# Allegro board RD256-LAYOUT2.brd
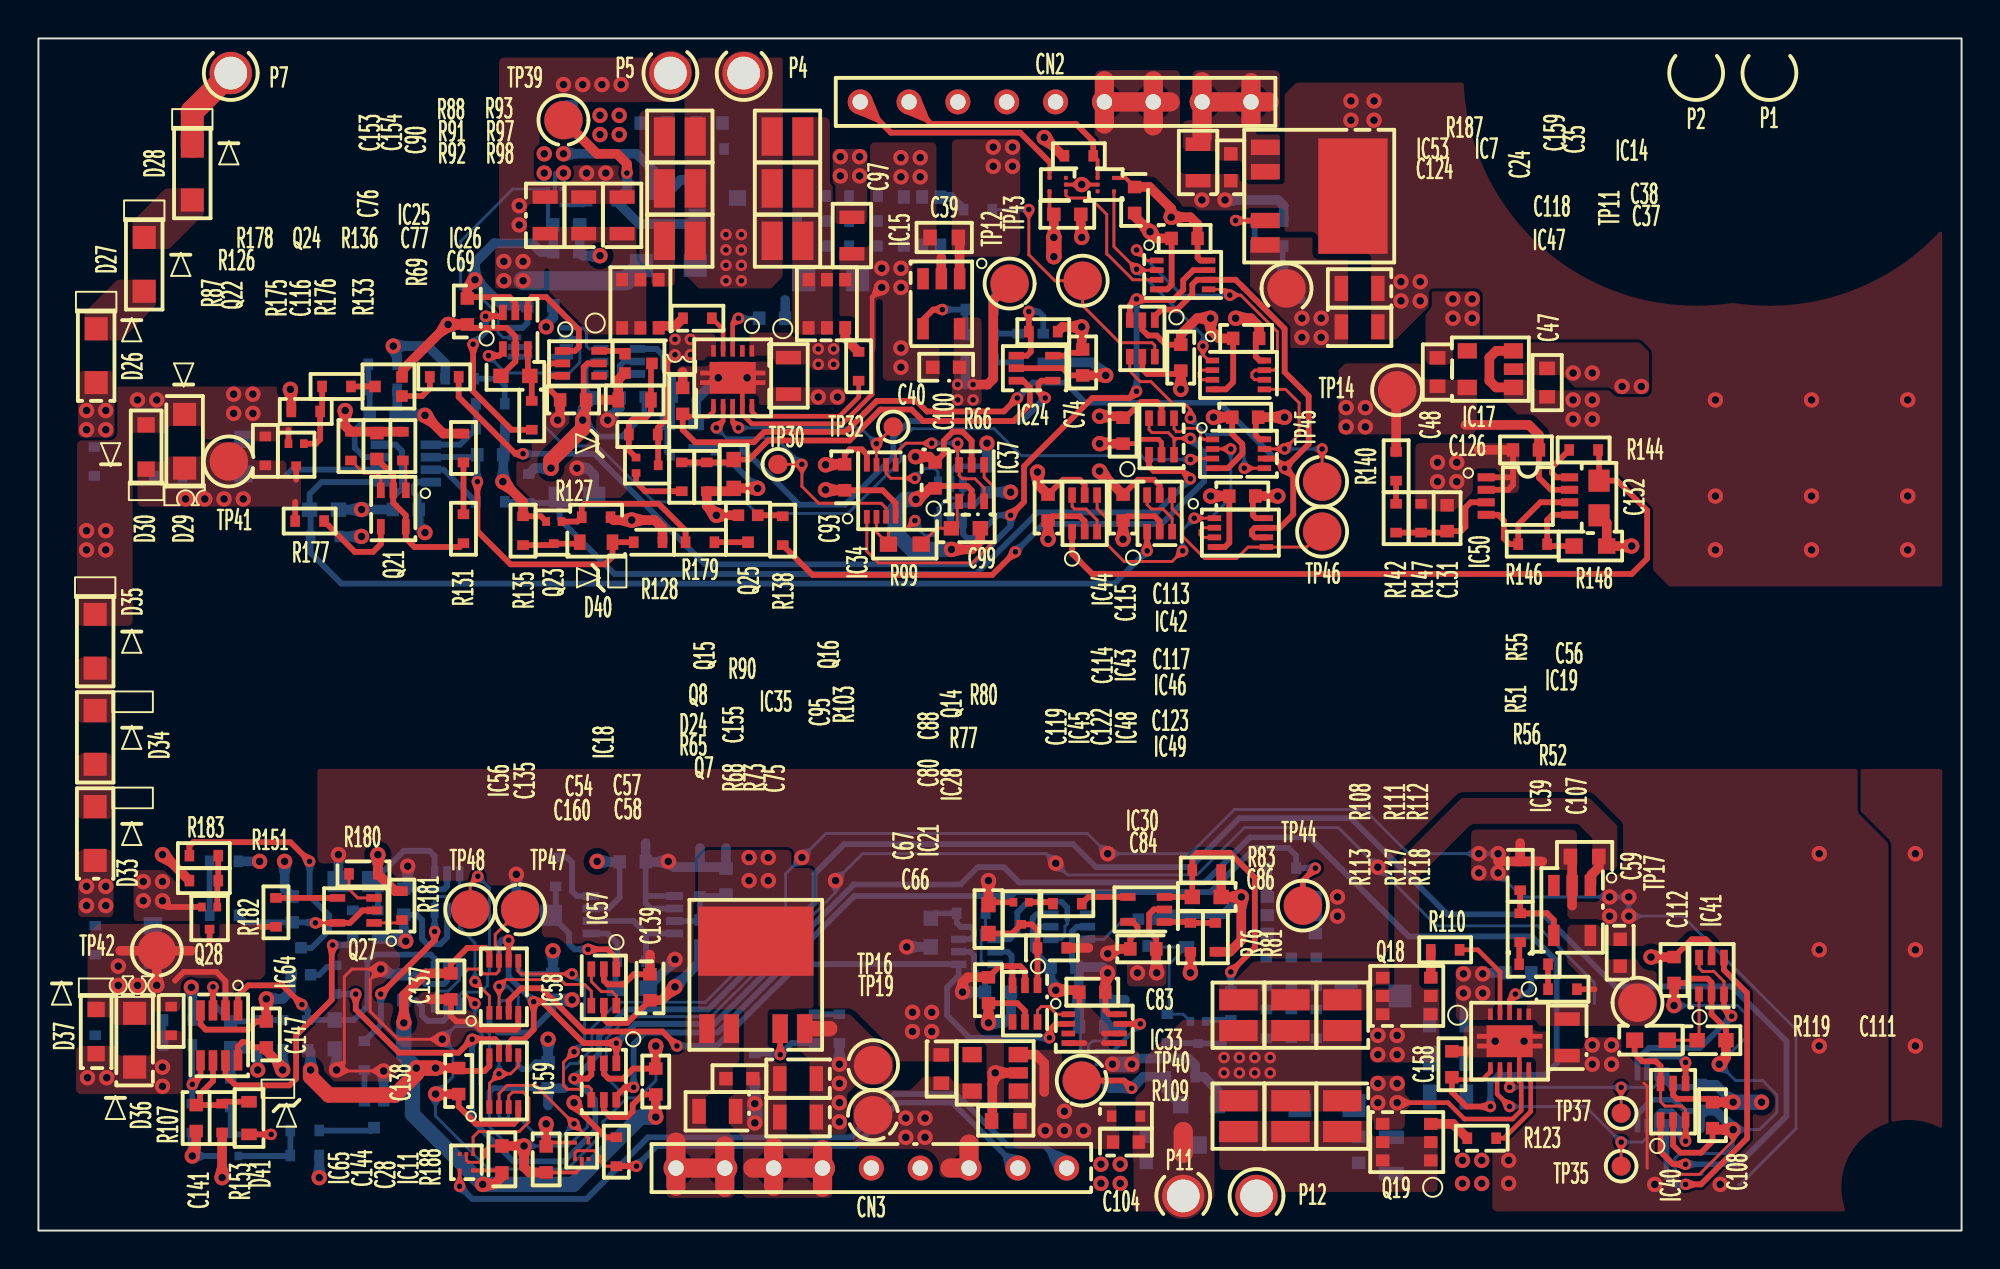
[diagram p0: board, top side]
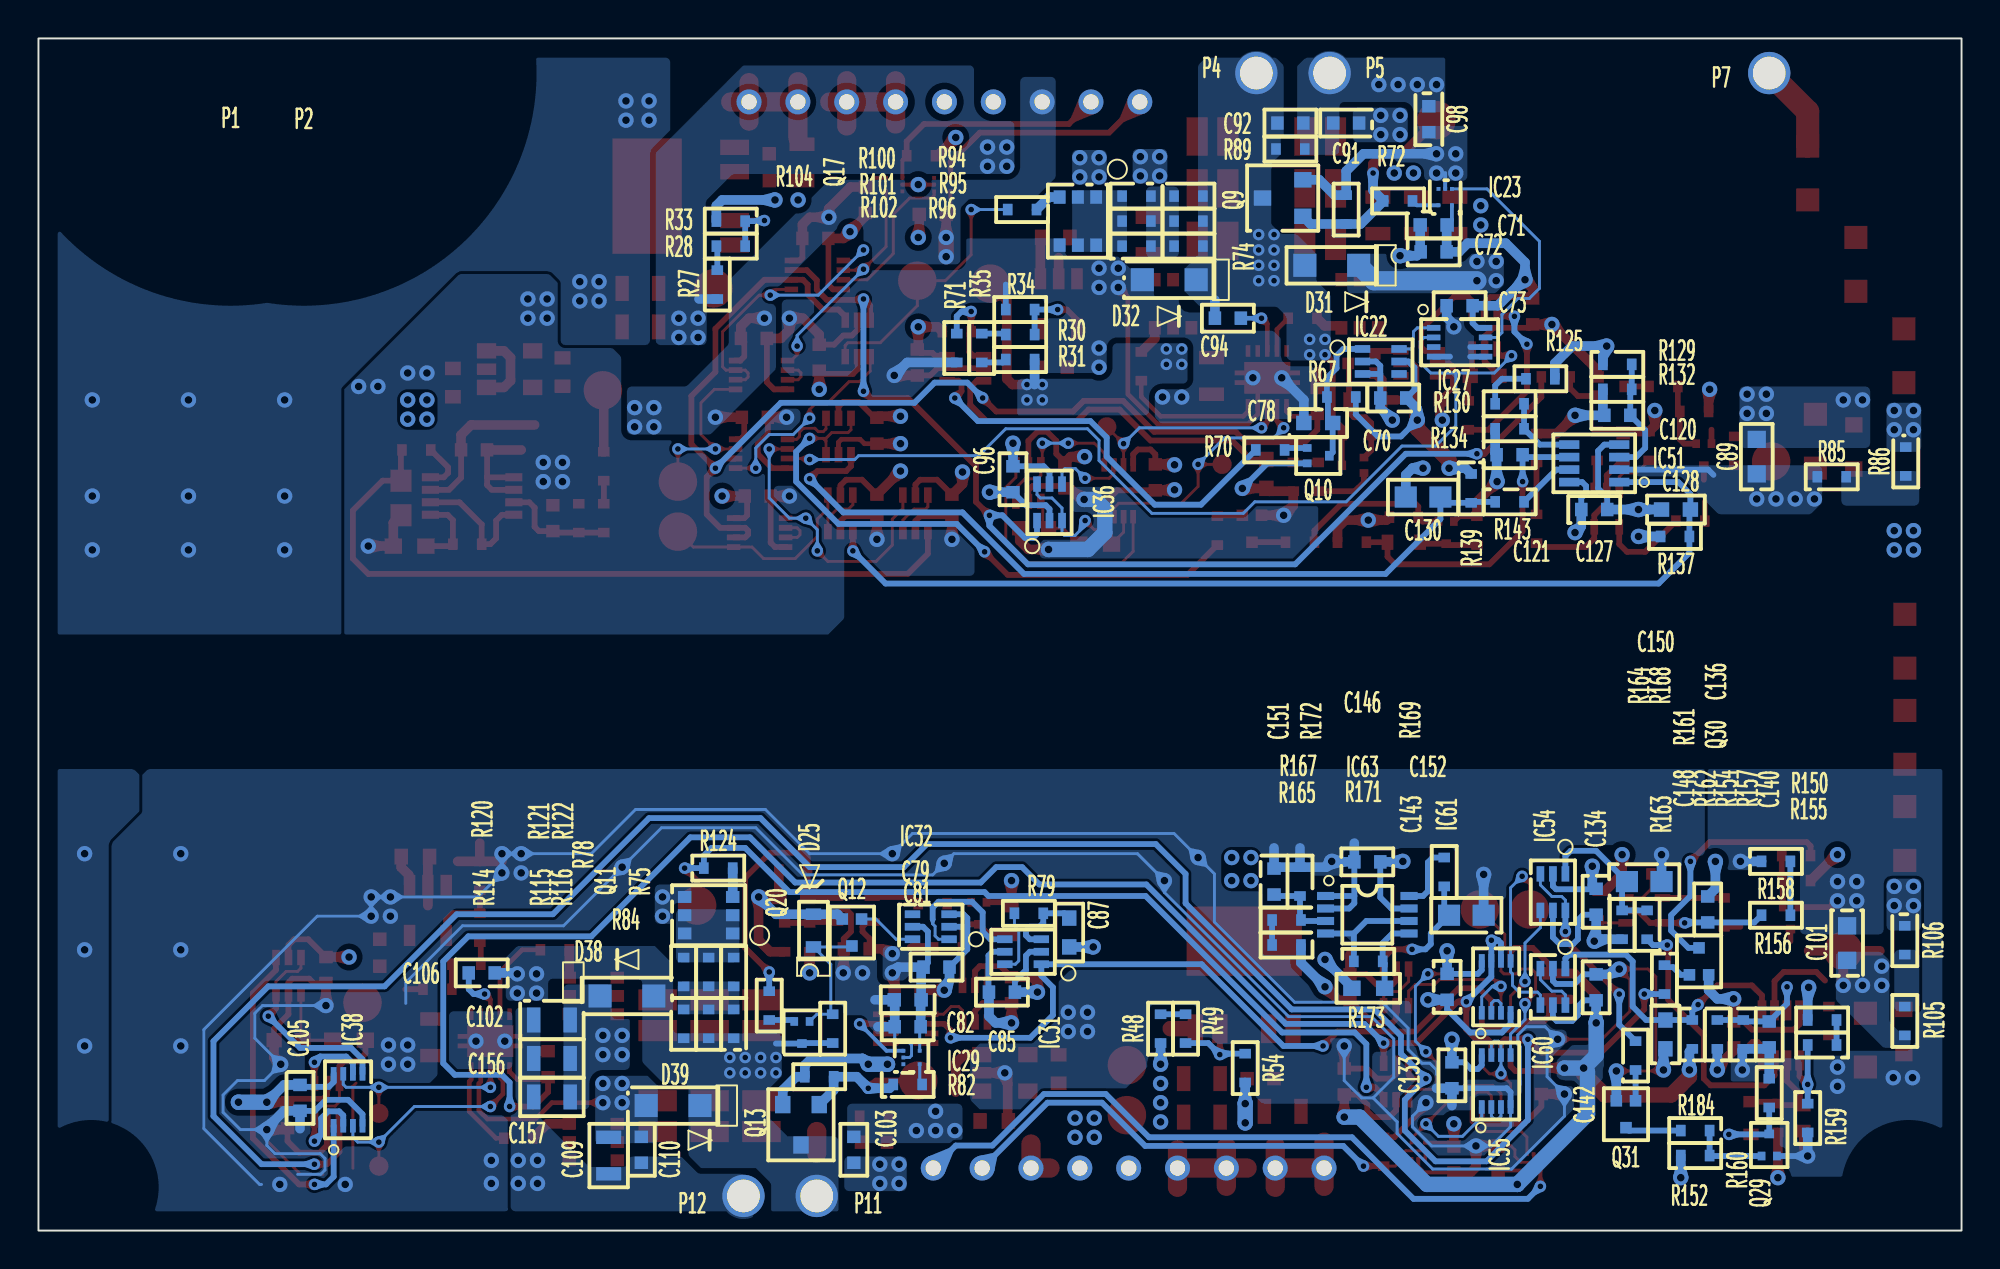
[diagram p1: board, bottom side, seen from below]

Outline 100 x 62 mm; copper layers: TOP, CONDUCTIVE2, CONDUCTIVE3, BOTTOM. Coordinates in mm from the lower left corner of the outline.
Outline path: rectangle 0,0 100,62

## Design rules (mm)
constraint set DEFAULT: 

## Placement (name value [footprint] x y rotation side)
C24  -  [C_CHP_MURATA_L1_6W0_8H0_8A]  57 53.6 270 top
C28  -  [C_CHP_MURATA_L1_6W0_8H0_8A]  26.4 3.7 270 top
C35  -  [C_CHP_TDK_L1_6W0_8H0_8]  62 55.3 90 top
C37  -  [C_CHP_MURATA_L2_0W1_25H1_25]  68.7 47 180 top
C38  -  [C_CHP_MURATA_L2_0W1_25H1_25]  68.7 49 180 top
C39  -  [C_CHP_TYYDN_L1_6W0_8H0_8A]  47.1 51.65 0 top
C40  -  [C_CHP_TDK_L1_6W0_8H0_8]  47.2 44.9 0 top
C47  -  [C_CHP_TYYDN_L1_6W0_8H0_8A]  78.45 44.1 270 top
C48  -  [C_CHP_TYYDN_L1_6W0_8H0_8A]  72.75 44.65 270 top
C54  -  [C_CHP_TDK_L1_6W0_8H0_8]  36.45 7.9 180 top
C56  -  [C_CHP_TYYDN_L1_6W0_8H0_8A]  80.4 19.45 0 top
C57  -  [C_CHP_MURATA_L2_0W1_25H1_25]  39.5 7.9 0 top
C58  -  [C_CHP_MURATA_L2_0W1_25H1_25]  39.5 5.9 0 top
C59  -  [C_CHP_TDK_L1_6W0_8H0_8]  82.25 14.45 270 top
C66  -  [C_CHP_TYYDN_L1_6W0_8H0_8A]  50.3 5.7 0 top
C67  -  [C_CHP_TYYDN_L1_6W0_8H0_8A]  46.95 8.4 270 top
C69  -  [C_CHP_MURATA_L1_6W0_8H0_8A]  27.8 43.2 0 top
C70  -  [C_CHP_MURATA_L1_6W0_8H0_8A]  29.55 43.3 180 bottom
C71  -  [C_CHP_TDK_L1_6W0_8H0_8]  27.45 52.3 180 bottom
C72  -  [C_CHP_MURATA_L1_6W0_8H0_8A]  27.45 50.9 180 bottom
C73  -  [C_CHP_MURATA_L1_6W0_8H0_8A]  26.1 48.1 180 bottom
C74  -  [C_CHP_MURATA_L1_6W0_8H0_8A]  54.3 45.15 90 top
C75  -  [C_CHP_AVX_L1_6W0_81H0_9]  36.15 39.35 90 top
C76  -  [C_CHP_MURATA_L1_6W0_8H0_8A]  22.3 47.8 90 top
C77  -  [C_CHP_AVX_L1_6W0_81H0_9]  24.8 44.45 0 top
C78  -  [C_CHP_AVX_L1_6W0_81H0_9]  33.45 42 180 bottom
C79  -  [C_CHP_MURATA_L1_6W0_8H0_8A]  53.3 13.7 0 bottom
C80  -  [C_CHP_MURATA_L1_6W0_8H0_8A]  49.4 12.5 270 top
C81  -  [C_CHP_TDK_L1_6W0_8H0_8]  54.8 12 180 bottom
C82  -  [C_CHP_MURATA_L1_6W0_8H0_8A]  54.8 10.6 180 bottom
C83  -  [C_CHP_MURATA_L1_6W0_8H0_8A]  54.8 12.4 0 top
C84  -  [C_CHP_MURATA_L1_6W0_8H0_8A]  57.45 14.65 180 top
C85  -  [C_CHP_MURATA_L1_6W0_8H0_8A]  49.9 12.4 0 bottom
C86  -  [C_CHP_AVX_L1_6W0_81H0_9]  60.75 17.35 180 top
C87  -  [C_CHP_AVX_L1_6W0_81H0_9]  46.4 15.5 90 bottom
C88  -  [C_CHP_AVX_L1_6W0_81H0_9]  49.4 16.2 270 top
C89  -  [C_CHP_AVX_L1_6W0_8H0_9]  10.65 40.25 270 bottom
C90  -  [C_CHP_MURATA_L2_0W1_25H1_25]  30.35 52.8 270 top
C91  -  [C_CHP_MURATA_L1_6W0_8H0_8A]  32 57.6 180 bottom
C92  -  [C_CHP_MURATA_L1_6W0_8H0_8A]  34.9 57.6 180 bottom
C93  -  [C_CHP_MURATA_L1_6W0_8H0_8A]  41.92 39.17 90 top
C94  -  [C_CHP_MURATA_L1_6W0_8H0_8A]  38.15 47.45 180 bottom
C95  -  [C_CHP_MURATA_L2_0W1_25H1_25]  39 44.45 90 top
C96  -  [C_CHP_MURATA_L1_6W0_8H0_8A]  49.33 39.08 90 bottom
C97  -  [C_CHP_MURATA_L2_0W1_25H1_25]  42.3 51.75 90 top
C98  -  [C_CHP_MURATA_L1_6W0_8H0_8A]  27.7 57.8 90 bottom
C99  -  [C_CHP_AVX_L1_6W0_81H0_9]  48.23 36.52 180 top
C100  -  [C_CHP_MURATA_L1_6W0_8H0_8A]  46.62 39.27 90 top
C101  -  [C_CHP_AVX_L1_6W0_8H0_9]  5.95 14.95 270 bottom
C102  -  [C_CHP_MURATA_L2_0W1_25H1_25]  73.3 10.95 180 bottom
C103  -  [C_CHP_MURATA_L1_6W0_8H0_8A]  57.6 4.2 270 bottom
C104  -  [C_CHP_MURATA_L1_6W0_8H0_8A]  56.55 4.6 180 top
C105  -  [C_CHP_MURATA_L1_6W0_8H0_8A]  86.4 6.9 90 bottom
C106  -  [C_CHP_MURATA_L1_6W0_8H0_8A]  76.95 13.4 0 bottom
C107  -  [C_CHP_MURATA_L2_0W1_25H1_25]  79.5 10.05 90 top
C108  -  [C_CHP_MURATA_L1_6W0_8H0_8A]  87.05 6 90 top
C109  -  [C_CHP_MURATA_L2_0W1_25H1_25]  70.35 3.9 270 bottom
C110  -  [C_CHP_MURATA_L1_6W0_8H0_8A]  68.65 4.2 270 bottom
C111  -  [C_CHP_AVX_L1_6W0_81H0_9]  87 9.9 180 top
C112  -  [C_CHP_MURATA_L1_6W0_8H0_8A]  85.05 13.55 90 top
C113  -  [C_CHP_MURATA_L1_6W0_8H0_8A]  62.8 46.4 0 top
C114  -  [C_CHP_MURATA_L1_6W0_8H0_8A]  56.4 41.6 270 top
C115  -  [C_CHP_MURATA_L1_6W0_8H0_8A]  59.4 45.4 90 top
C116  -  [C_CHP_MURATA_L1_6W0_8H0_8A]  17.6 40.8 90 top
C117  -  [C_CHP_MURATA_L1_6W0_8H0_8A]  62.75 42.3 0 top
C118  -  [C_CHP_MURATA_L1_6W0_8H0_8A]  59.6 51.6 0 top
C119  -  [C_CHP_MURATA_L1_6W0_8H0_8A]  52.5 37.6 270 top
C120  -  [C_CHP_MURATA_L1_6W0_8H0_8A]  17.9 42.4 180 bottom
C121  -  [C_CHP_MURATA_L1_6W0_8H0_8A]  23.5 40.35 180 bottom
C122  -  [C_CHP_MURATA_L1_6W0_8H0_8A]  56.4 37.6 270 top
C123  -  [C_CHP_MURATA_L1_6W0_8H0_8A]  62.6 38.2 0 top
C124  -  [C_CHP_TDK_L1_6W0_8H0_8]  53.5 52.85 0 top
C126  -  [C_CHP_MURATA_L1_6W0_8H0_8A]  77.35 40.6 0 top
C127  -  [C_CHP_MURATA_L1_6W0_8H0_8A]  19.1 37.5 0 bottom
C128  -  [C_CHP_AVX_L1_6W0_81H0_9]  14.85 37.5 180 bottom
C130  -  [C_CHP_KEMET_L1_6W0_8H0_8]  28 38.15 180 bottom
C131  -  [C_CHP_MURATA_L1_6W0_8H0_8A]  73.25 37.05 270 top
C132  -  [C_CHP_KEMET_L1_6W0_8H0_8]  81.15 38.1 90 top
C133  -  [C_CHP_MURATA_L1_6W0_8H0_8A]  26.5 8.07 90 bottom
C134  -  [C_CHP_MURATA_L1_6W0_8H0_8A]  19 17.1 90 bottom
C135  -  [C_CHP_MURATA_L1_6W0_8H0_8A]  32.1 7.75 90 top
C136  -  [C_CHP_MURATA_L1_6W0_8H0_8A]  13.2 16.7 90 bottom
C137  -  [C_CHP_MURATA_L1_6W0_8H0_8A]  21.45 12.7 90 top
C138  -  [C_CHP_MURATA_L1_6W0_8H0_8A]  21.85 7.78 90 top
C139  -  [C_CHP_MURATA_L1_6W0_8H0_8A]  31.8 12.65 90 top
C140  -  [C_CHP_MURATA_L1_6W0_8H0_8A]  10 10.2 90 bottom
C141  -  [C_CHP_MURATA_L1_6W0_8H0_8A]  8.2 5.85 90 top
C142  -  [C_CHP_MURATA_L1_6W0_8H0_8A]  19 12.65 90 bottom
C143  -  [C_CHP_MURATA_L1_6W0_8H0_8A]  26.75 12.68 90 bottom
C144  -  [C_CHP_TDK_L1_6W0_8H0_8]  24.1 3.7 90 top
C146  -  [C_CHP_MURATA_L1_6W0_8H0_8A]  30.9 19.18 180 bottom
C147  -  [C_CHP_MURATA_L1_6W0_8H0_8A]  11.85 10.2 270 top
C148  -  [C_CHP_AVX_L1_6W0_81H0_9]  15.4 10.2 90 bottom
C150  -  [C_CHP_KEMET_L1_6W0_8H0_8]  16.5 18.15 0 bottom
C151  -  [C_CHP_MURATA_L1_6W0_8H0_8A]  35.75 18.15 270 bottom
C152  -  [C_CHP_KEMET_L1_6W0_8H0_8]  25.75 16.4 0 bottom
C153  -  [C_CHP_MURATA_L2_0W1_25H1_25]  26.35 52.8 270 top
C154  -  [C_CHP_MURATA_L2_0W1_25H1_25]  28.35 52.8 270 top
C155  -  [C_CHP_MURATA_L1_6W0_8H0_8A]  33.5 43.15 90 top
C156  -  [C_CHP_MURATA_L2_0W1_25H1_25]  73.3 8.95 180 bottom
C157  -  [C_CHP_MURATA_L2_0W1_25H1_25]  73.3 6.95 180 bottom
C158  -  [C_CHP_MURATA_L1_6W0_8H0_8A]  73.5 8.65 90 top
C159  -  [C_CHP_MURATA_L2_0W1_25H1_25]  60.3 55.55 90 top
C160  -  [C_CHP_MURATA_L2_0W1_25H1_25]  35.3 6.2 180 top
CN2  -  [PM_61_9P]  63.05 58.7 180 top
CN3  -  [PM_61_9P]  33.15 3.25 0 top
D24  -  [ZD_SMD_TSB_K_1_A_2_L1_2W0_8H0_6]  31 43.2 180 top
D25  -  [ZD_SMD_TSB_K_1_A_2_L1_2W0_8H0_6]  59.7 15.6 90 bottom
D26  -  [D_SMD_TSB_K_2_A_1_L2_6W1_6H0_98]  3 45.5 270 top
D27  -  [D_SMD_TSB_K_2_A_1_L2_6W1_6H0_98]  5.5 50.25 270 top
D28  -  [D_SMD_TSB_K_2_A_1_L2_6W1_6H0_98]  8 55 270 top
D29  -  [D_SMD_TSB_K_2_A_1_L2_6W1_6H0_98]  7.6 41.05 90 top
D30  -  [D_SMD_TSB_K_2_A_1_L1_7W1_25H0_9]  5.6 40.75 90 top
D31  -  [D_SMD_TSB_K_2_A_1_L2_6W1_6H0_98]  32.75 50.2 0 bottom
D32  -  [D_SMD_TSB_K_2_A_1_L2_6W1_6H0_98]  41.2 49.45 0 bottom
D33  -  [D_SMD_TSB_K_2_A_1_L2_6W1_6H0_98]  2.95 20.65 270 top
D34  -  [D_SMD_TSB_K_2_A_1_L2_6W1_6H0_98]  2.95 25.65 270 top
D35  -  [D_SMD_TSB_K_2_A_1_L2_6W1_6H0_98]  2.95 30.65 270 top
D36  -  [D_SMD_TSB_K_2_A_1_L2_6W1_6H0_98]  5 9.9 270 top
D37  -  [D_SMD_TSB_K_2_A_1_L1_7W1_25H0_9]  3 10.35 270 top
D38  -  [D_SMD_TSB_K_2_A_1_L2_6W1_6H0_98]  69.4 12.2 180 bottom
D39  -  [D_SMD_TSB_K_2_A_1_L2_6W1_6H0_98]  67 6.5 0 bottom
D40  -  [ZD_SMD_TSB_K_1_A_2_L1_2W0_8H0_6]  29 35.8 180 top
D41  -  [ZD_SMD_TSB_K_1_A_2_L1_2W0_8H0_6]  10.95 5.85 270 top
IC7  -  [IC_SMD_5_TSB_L1_0W0_8H0_48_RCNT]  55.5 54.4 270 top
IC11  -  [IC_SMD_5_TSB_L1_0W0_8H0_48_RCNT]  28.25 4.15 0 top
IC14  -  [REG_TO_252_5S_A_ABLIC_L6_5W4_7H1_4]  67.1 53.8 270 top
IC15  -  [IC_SOP_5_TI_L3_05W1_75H1_45]  46.95 48.2 180 top
IC17  -  [IC_SC74A_TSB_L2_9W1_6H1_15_RP0_05]  75.5 44.8 90 top
IC18  -  [REG_TO_252_5S_A_ABLIC_L6_5W4_7H1_4]  37.3 13.8 0 top
IC19  -  [IC_SOP_5_TI_L3_05W1_75H1_45]  79.75 16.65 180 top
IC21  -  [IC_SC74A_TSB_L2_9W1_6H1_15_RP0_05]  49.75 8.2 90 top
IC22  -  [IC_SOP_6_TSB_L2_0W1_25H0_95_RP0_05]  30.2 45.2 270 bottom
IC23  -  [IC_SMD_5_TSB_L1_0W0_8H0_48_RCNT]  26.85 53.75 0 bottom
IC24  -  [IC_SC88A_TSB_L2_0W1_25H0_95_RP0_05]  51.8 44.85 270 top
IC25  -  [IC_SOP_6_TSB_L2_0W1_25H0_95_RP0_05]  24.8 46.8 0 top
IC26  -  [IC_SOP_6_TSB_L2_0W1_25H0_95_RP0_05]  28.2 45.1 270 top
IC27  -  [IC_SOP_8_TSB_L2_0W2_3H0_75_P0_5_RP0_05]  26.1 46.2 270 bottom
IC28  -  [IC_SOP_6_TSB_L2_0W1_25H0_95_RP0_05]  51.3 11.8 180 top
IC29  -  [IC_SMD_5_TSB_L1_0W0_8H0_48_RCNT]  54.6 9 270 bottom
IC30  -  [IC_SC88A_TSB_L2_0W1_25H0_95_RP0_05]  57.6 16.7 90 top
IC31  -  [IC_SOP_6_TSB_L2_0W1_25H0_95_RP0_05]  48.8 14.5 90 bottom
IC32  -  [IC_SOP_6_TSB_L2_0W1_25H0_95_RP0_05]  53.6 15.8 90 bottom
IC33  -  [IC_SOP_8_TSB_L2_0W2_3H0_75_P0_5_RP0_05]  54.9 10.5 270 top
IC34  -  [IC_SOP_8_TSB_L2_0W2_3H0_75_P0_5_RP0_05]  43.83 38.48 0 top
IC35  -  [IC_SON_10S1_TI_L3_1W3_1H1_0_RP0_05_2]  36.1 44.35 180 top
IC36  -  [IC_SOP_6_TSB_L2_0W1_25H0_95_RP0_05]  47.42 37.88 180 bottom
IC37  -  [IC_SOP_6_TSB_L2_0W1_25H0_95_RP0_05]  48.52 38.88 0 top
IC38  -  [IC_SOP_8_TSB_L2_0W2_3H0_75_P0_5_RP0_05]  83.9 6.8 180 bottom
IC39  -  [IC_SON_10S1_TI_L3_1W3_1H1_0_RP0_05_2]  76.5 9.85 180 top
IC40  -  [IC_SOP_6_TSB_L2_0W1_25H0_95_RP0_05]  85 6.7 0 top
IC41  -  [IC_SOP_6_TSB_L2_0W1_25H0_95_RP0_05]  87 13.25 0 top
IC42  -  [IC_SOP_8_TSB_L2_0W2_3H0_75_P0_5_RP0_05]  62.4 44.5 270 top
IC43  -  [IC_SOP_6_TSB_L2_0W1_25H0_95_RP0_05]  58.4 41.3 0 top
IC44  -  [IC_SOP_6_TSB_L2_0W1_25H0_95_RP0_05]  57.4 46.4 180 top
IC45  -  [IC_SOP_6_TSB_L2_0W1_25H0_95_RP0_05]  54.4 37.3 0 top
IC46  -  [IC_SOP_8_TSB_L2_0W2_3H0_75_P0_5_RP0_05]  62.4 40.4 270 top
IC47  -  [IC_SOP_8_TSB_L2_0W2_3H0_75_P0_5_RP0_05]  59.5 49.7 270 top
IC48  -  [IC_SOP_6_TSB_L2_0W1_25H0_95_RP0_05]  58.3 37.3 0 top
IC49  -  [IC_SOP_8_TSB_L2_0W2_3H0_75_P0_5_RP0_05]  62.5 36.3 270 top
IC50  -  [IC_MS8_LINEAR_L3_0W3_0H1_1_P0_65]  77.45 38.2 270 top
IC51  -  [IC_DDF_TI_L2_9W1_6H1_1_P0_65]  19.1 39.9 90 bottom
IC53  -  [IC_SMD_5_TSB_L1_0W0_8H0_48_RCNT]  53 54.4 90 top
IC54  -  [IC_SOP_6_TSB_L2_0W1_25H0_95_RP0_05]  21.25 17.6 0 bottom
IC55  -  [IC_SOP_8_TSB_L2_0W2_3H0_75_P0_5_RP0_05]  24.2 7.78 180 bottom
IC56  -  [IC_SOP_6_TSB_L2_0W1_25H0_95_RP0_05]  29.4 7.75 180 top
IC57  -  [IC_SOP_6_TSB_L2_0W1_25H0_95_RP0_05]  29.4 12.65 180 top
IC58  -  [IC_SOP_8_TSB_L2_0W2_3H0_75_P0_5_RP0_05]  24.2 12.68 0 top
IC59  -  [IC_SOP_8_TSB_L2_0W2_3H0_75_P0_5_RP0_05]  24.2 7.78 0 top
IC60  -  [IC_SOP_6_TSB_L2_0W1_25H0_95_RP0_05]  21.25 12.68 0 bottom
IC61  -  [IC_SOP_8_TSB_L2_0W2_3H0_75_P0_5_RP0_05]  24.2 12.68 180 bottom
IC63  -  [IC_MS8_LINEAR_L3_0W3_0H1_1_P0_65]  30.9 16.43 270 bottom
IC64  -  [IC_DDF_TI_L2_9W1_6H1_1_P0_65]  9.4 10.15 180 top
IC65  -  [IC_SMD_5_TSB_L1_0W0_8H0_48_RCNT]  22.25 3.55 180 top
NOREF  -  []  86.2 60.2 90 top
NOREF#2  -  []  90.01 60.2 90 top
P4  -  [ITNS_TH1_7_P_C2_2_RP0_05]  36.67 60.2 0 top
P5  -  [ITNS_TH1_7_P_C2_2_RP0_05]  32.86 60.2 0 top
P7  -  [ITNS_TH1_7_P_C2_2_RP0_05]  10 60.2 0 top
P11  -  [ITNS_TH1_7_P_C2_2_RP0_05]  59.53 1.8 0 top
P12  -  [ITNS_TH1_7_P_C2_2_RP0_05]  63.34 1.8 0 top
Q7  -  [TR_SMD_3_TSB_B_1_E_2_C_3_L1_2W0_8H0_5]  31.65 39.8 270 top
Q8  -  [FET_SMD_TSB_G_1_S_2_D_3_L1_6W0_8H0_75]  31.2 45.1 270 top
Q9  -  [FET_SMD_TSB_L2_9W1_8H0_8]  35.3 53.7 90 bottom
Q10  -  [TR_SMD_3_TSB_B_1_E_2_C_3_L1_2W0_8H0_5]  33.45 40.3 270 bottom
Q11  -  [TR_SMD_3_TSB_B_1_E_2_C_3_L1_2W0_8H0_5]  60.3 10.3 0 bottom
Q12  -  [FET_SMD_TSB_G_1_S_2_D_3_L1_6W0_8H0_75]  57.7 15.5 0 bottom
Q13  -  [FET_SMD_TSB_L2_9W1_8H0_8]  60.35 5.5 0 bottom
Q14  -  [TR_SMD_3_TSB_B_1_E_2_C_3_L1_2W0_8H0_5]  51.1 16.5 180 top
Q15  -  [FET_SMD_TSB_D_1_2_5_6_G_3_S_4_L2_9W2_2H0_8_RP0_05]  31.3 48.2 0 top
Q16  -  [FET_SMD_TSB_D_1_2_5_6_G_3_S_4_L2_9W2_2H0_8_RP0_05]  41 48.2 0 top
Q17  -  [FET_SMD_TSB_D_1_2_5_6_G_3_S_4_L2_9W2_2H0_8_RP0_05]  45.95 52.5 0 bottom
Q18  -  [FET_SMD_TSB_D_1_2_5_6_G_3_S_4_L2_9W2_2H0_8_RP0_05]  71.15 12.2 90 top
Q19  -  [FET_SMD_TSB_D_1_2_5_6_G_3_S_4_L2_9W2_2H0_8_RP0_05]  71.15 4.6 90 top
Q20  -  [FET_SMD_TSB_D_1_2_5_6_G_3_S_4_L2_9W2_2H0_8_RP0_05]  65.15 16.4 90 bottom
Q21  -  [TR_USV_TSB_L2_0W1_25H1_1]  18.45 37.55 180 top
Q22  -  [TR_SMD_3_TSB_B_1_E_2_C_3_L1_2W0_8H0_5]  13.4 40.35 180 top
Q23  -  [TR_SMD_3_TSB_B_1_E_2_C_3_L1_2W0_8H0_5]  26.8 36.3 180 top
Q24  -  [FET_SMD_TSB_G_1_S_2_D_3_L1_6W0_8H0_75]  18.2 43.9 90 top
Q25  -  [FET_SMD_TSB_G_1_S_2_D_3_L1_6W0_8H0_75]  36.9 36.5 180 top
Q27  -  [TR_USV_TSB_L2_0W1_25H1_1]  16.5 16.65 90 top
Q28  -  [TR_SMD_3_TSB_B_1_E_2_C_3_L1_2W0_8H0_5]  8.9 16.25 180 top
Q29  -  [TR_SMD_3_TSB_B_1_E_2_C_3_L1_2W0_8H0_5]  10 4.45 180 bottom
Q30  -  [FET_SMD_TSB_G_1_S_2_D_3_L1_6W0_8H0_75]  13.65 14 180 bottom
Q31  -  [FET_SMD_TSB_G_1_S_2_D_3_L1_6W0_8H0_75]  17.45 6.05 0 bottom
R27  -  [R_CHP_KOA_L1_6W0_8H0_45]  64.7 49.2 270 bottom
R28  -  [R_CHP_KOA_L1_6W0_8H0_45]  64 51.2 0 bottom
R30  -  [R_CHP_KOA_L1_6W0_8H0_45]  48.95 46.6 0 bottom
R31  -  [R_CHP_KOA_L1_6W0_8H0_45]  48.95 45.3 180 bottom
R33  -  [R_CHP_KOA_L1_6W0_8H0_45]  64 52.5 180 bottom
R34  -  [R_CHP_KOA_L1_6W0_8H0_45]  48.95 47.9 180 bottom
R35  -  [R_CHP_KOA_L1_6W0_8H0_45]  50.95 45.9 270 bottom
R48  -  [R_CHP_KOA_L1_6W0_8H0_45]  41.65 10.5 270 bottom
R49  -  [R_CHP_KOA_L1_6W0_8H0_45]  40.35 10.5 90 bottom
R51  -  [R_CHP_KOA_L1_6W0_8H0_45]  77.05 15.75 270 top
R52  -  [R_CHP_KOA_L1_6W0_8H0_45]  79.25 12.55 0 top
R54  -  [R_CHP_KOA_L1_6W0_8H0_45]  37.25 8.45 90 bottom
R55  -  [R_CHP_KOA_L1_6W0_8H0_45]  77.05 18.45 270 top
R56  -  [R_CHP_KOA_L1_6W0_8H0_45]  77.75 13.85 0 top
R65  -  [R_CHP_KOA_L1_6W0_8H0_45]  31.45 41.4 0 top
R66  -  [R_CHP_KOA_L1_6W0_8H0_45]  52.25 46.75 0 top
R67  -  [R_CHP_KOA_L1_6W0_8H0_45]  32.25 43.35 180 bottom
R68  -  [R_CHP_KOA_L1_6W0_8H0_45]  33.45 39.2 270 top
R69  -  [R_CHP_KOA_L1_6W0_8H0_45]  25.65 42.4 90 top
R70  -  [R_CHP_KOA_L1_6W0_8H0_45]  35.95 40.6 0 bottom
R71  -  [R_CHP_KOA_L1_6W0_8H0_45]  52.25 45.9 90 bottom
R72  -  [R_CHP_KOA_L1_6W0_8H0_45]  29.3 53.55 0 bottom
R73  -  [R_CHP_KOA_L1_6W0_8H0_45]  34.75 39.2 90 top
R74  -  [R_CHP_KOA_L1_6W0_8H0_45]  32 53.1 270 bottom
R75  -  [R_CHP_KOA_L1_6W0_8H0_45]  58.7 10.5 270 bottom
R76  -  [R_CHP_KOA_L1_6W0_8H0_45]  59.9 15.25 270 top
R77  -  [R_CHP_KOA_L1_6W0_8H0_45]  52.7 14.7 0 top
R78  -  [R_CHP_KOA_L1_6W0_8H0_45]  62 11.7 270 bottom
R79  -  [R_CHP_KOA_L1_6W0_8H0_45]  48.5 16.5 180 bottom
R80  -  [R_CHP_KOA_L1_6W0_8H0_45]  53.5 17 0 top
R81  -  [R_CHP_KOA_L1_6W0_8H0_45]  61.2 15.25 90 top
R82  -  [R_CHP_KOA_L1_6W0_8H0_45]  54.8 7.6 0 bottom
R83  -  [R_CHP_KOA_L1_6W0_8H0_45]  60.75 18.75 180 top
R84  -  [R_CHP_KOA_L1_6W0_8H0_45]  59.4 8 180 bottom
R85  -  [R_CHP_KOA_L1_6W0_8H0_45]  6.75 39.2 180 bottom
R86  -  [R_CHP_KOA_L1_6W0_8H0_45]  2.9 40 90 bottom
R87  -  [R_CHP_KOA_L1_6W0_8H0_45]  11.8 40.55 270 top
R88  -  [R_CHP_ROHM_L2_0W1_2H0_55]  33.35 56.9 270 top
R89  -  [R_CHP_KOA_L1_6W0_8H0_45]  34.9 56.25 180 bottom
R90  -  [R_CHP_KOA_L1_6W0_8H0_45]  34.27 47.45 180 top
R91  -  [R_CHP_ROHM_L2_0W1_2H0_55]  33.35 54.2 270 top
R92  -  [R_CHP_ROHM_L2_0W1_2H0_55]  33.35 51.48 270 top
R93  -  [R_CHP_ROHM_L2_0W1_2H0_55]  38.95 56.9 90 top
R94  -  [R_CHP_KOA_L1_6W0_8H0_45]  40.2 53.8 180 bottom
R95  -  [R_CHP_KOA_L1_6W0_8H0_45]  40.2 52.5 180 bottom
R96  -  [R_CHP_KOA_L1_6W0_8H0_45]  40.2 51.2 180 bottom
R97  -  [R_CHP_ROHM_L2_0W1_2H0_55]  38.95 54.2 90 top
R98  -  [R_CHP_ROHM_L2_0W1_2H0_55]  38.95 51.48 90 top
R99  -  [R_CHP_YAGEO_L1_6W0_8H0_45]  45.05 35.7 0 top
R100  -  [R_CHP_KOA_L1_6W0_8H0_45]  42.9 53.8 180 bottom
R101  -  [R_CHP_KOA_L1_6W0_8H0_45]  42.9 52.5 180 bottom
R102  -  [R_CHP_KOA_L1_6W0_8H0_45]  42.9 51.2 180 bottom
R103  -  [R_CHP_KOA_L1_6W0_8H0_45]  42.65 44.95 90 top
R104  -  [R_CHP_KOA_L1_6W0_8H0_45]  48.85 53.1 180 bottom
R105  -  [R_CHP_KOA_L1_6W0_8H0_45]  2.95 10.9 90 bottom
R106  -  [R_CHP_KOA_L1_6W0_8H0_45]  2.95 15.1 90 bottom
R107  -  [R_CHP_KOA_L1_6W0_8H0_45]  6.9 10.9 90 top
R108  -  [R_CHP_ROHM_L2_0W1_2H0_55]  62.4 11.2 180 top
R109  -  [R_CHP_KOA_L1_6W0_8H0_45]  56.55 5.95 180 top
R110  -  [R_CHP_KOA_L1_6W0_8H0_45]  73.15 14.6 180 top
R111  -  [R_CHP_ROHM_L2_0W1_2H0_55]  65.1 11.2 180 top
R112  -  [R_CHP_ROHM_L2_0W1_2H0_55]  67.8 11.2 180 top
R113  -  [R_CHP_ROHM_L2_0W1_2H0_55]  62.4 5.95 0 top
R114  -  [R_CHP_KOA_L1_6W0_8H0_45]  66.45 10.75 270 bottom
R115  -  [R_CHP_KOA_L1_6W0_8H0_45]  65.15 10.75 270 bottom
R116  -  [R_CHP_KOA_L1_6W0_8H0_45]  63.85 10.75 270 bottom
R117  -  [R_CHP_ROHM_L2_0W1_2H0_55]  65.1 5.95 0 top
R118  -  [R_CHP_ROHM_L2_0W1_2H0_55]  67.8 5.95 0 top
R119  -  [R_CHP_YAGEO_L1_6W0_8H0_45]  83.85 9.9 0 top
R120  -  [R_CHP_KOA_L1_6W0_8H0_45]  66.45 13.45 270 bottom
R121  -  [R_CHP_KOA_L1_6W0_8H0_45]  65.15 13.45 270 bottom
R122  -  [R_CHP_KOA_L1_6W0_8H0_45]  63.85 13.45 270 bottom
R123  -  [R_CHP_KOA_L1_6W0_8H0_45]  75.05 4.8 180 top
R124  -  [R_CHP_KOA_L1_6W0_8H0_45]  64.65 18.85 180 bottom
R125  -  [R_CHP_KOA_L1_6W0_8H0_45]  21.9 44.3 180 bottom
R126  -  [R_CHP_KOA_L1_6W0_8H0_45]  13.9 42.6 180 top
R127  -  [R_CHP_KOA_L1_6W0_8H0_45]  29 37.1 0 top
R128  -  [R_CHP_KOA_L1_6W0_8H0_45]  31.7 35.8 0 top
R129  -  [R_CHP_KOA_L1_6W0_8H0_45]  17.9 45.05 0 bottom
R130  -  [R_CHP_KOA_L1_6W0_8H0_45]  23.5 43 0 bottom
R131  -  [R_CHP_KOA_L1_6W0_8H0_45]  22.1 36.5 270 top
R132  -  [R_CHP_KOA_L1_6W0_8H0_45]  17.9 43.75 180 bottom
R133  -  [R_CHP_KOA_L1_6W0_8H0_45]  22.1 40.7 270 top
R134  -  [R_CHP_KOA_L1_6W0_8H0_45]  23.5 41.7 180 bottom
R135  -  [R_CHP_KOA_L1_6W0_8H0_45]  25.2 36.4 270 top
R136  -  [R_CHP_KOA_L1_6W0_8H0_45]  21.1 44.4 0 top
R137  -  [R_CHP_KOA_L1_6W0_8H0_45]  14.9 36.1 0 bottom
R138  -  [R_CHP_KOA_L1_6W0_8H0_45]  38.7 36.4 270 top
R139  -  [R_CHP_KOA_L1_6W0_8H0_45]  25.5 38.6 90 bottom
R140  -  [R_CHP_KOA_L1_6W0_8H0_45]  70.6 39.75 90 top
R142  -  [R_CHP_KOA_L1_6W0_8H0_45]  70.6 37.05 90 top
R143  -  [R_CHP_KOA_L1_6W0_8H0_45]  23.5 37.9 180 bottom
R144  -  [R_CHP_KOA_L1_6W0_8H0_45]  80.35 40.6 180 top
R146  -  [R_CHP_KOA_L1_6W0_8H0_45]  77.7 35.7 180 top
R147  -  [R_CHP_KOA_L1_6W0_8H0_45]  71.9 37.05 270 top
R148  -  [R_CHP_YAGEO_L1_6W0_8H0_45]  80.7 35.6 180 top
R150  -  [R_CHP_KOA_L1_6W0_8H0_45]  7.25 10.95 0 bottom
R151  -  [R_CHP_KOA_L1_6W0_8H0_45]  8.6 18.2 180 top
R152  -  [R_CHP_KOA_L1_6W0_8H0_45]  13.85 3.9 0 bottom
R153  -  [R_CHP_KOA_L1_6W0_8H0_45]  9.55 5.85 270 top
R154  -  [R_CHP_KOA_L1_6W0_8H0_45]  12.7 10.2 270 bottom
R155  -  [R_CHP_KOA_L1_6W0_8H0_45]  7.25 9.65 180 bottom
R156  -  [R_CHP_KOA_L1_6W0_8H0_45]  9.65 16.4 0 bottom
R157  -  [R_CHP_KOA_L1_6W0_8H0_45]  11.35 10.2 90 bottom
R158  -  [R_CHP_KOA_L1_6W0_8H0_45]  9.65 19.2 180 bottom
R159  -  [R_CHP_KOA_L1_6W0_8H0_45]  8 5.85 90 bottom
R160  -  [R_CHP_KOA_L1_6W0_8H0_45]  10 7.15 270 bottom
R161  -  [R_CHP_KOA_L1_6W0_8H0_45]  15.45 13.05 270 bottom
R162  -  [R_CHP_KOA_L1_6W0_8H0_45]  14 10.2 270 bottom
R163  -  [R_CHP_KOA_L1_6W0_8H0_45]  16.95 9.1 90 bottom
R164  -  [R_CHP_KOA_L1_6W0_8H0_45]  17.65 15.9 270 bottom
R165  -  [R_CHP_KOA_L1_6W0_8H0_45]  35.1 14.85 180 bottom
R167  -  [R_CHP_KOA_L1_6W0_8H0_45]  35.1 16.15 0 bottom
R168  -  [R_CHP_KOA_L1_6W0_8H0_45]  16.35 15.9 270 bottom
R169  -  [R_CHP_KOA_L1_6W0_8H0_45]  26.9 18.65 90 bottom
R171  -  [R_CHP_KOA_L1_6W0_8H0_45]  30.85 14 0 bottom
R172  -  [R_CHP_KOA_L1_6W0_8H0_45]  34.4 18.15 270 bottom
R173  -  [R_CHP_YAGEO_L1_6W0_8H0_45]  30.85 12.6 180 bottom
R175  -  [R_CHP_KOA_L1_6W0_8H0_45]  16.25 40.8 90 top
R176  -  [R_CHP_KOA_L1_6W0_8H0_45]  18.95 40.8 90 top
R177  -  [R_CHP_KOA_L1_6W0_8H0_45]  14.1 36.9 0 top
R178  -  [R_CHP_KOA_L1_6W0_8H0_45]  15.5 43.9 180 top
R179  -  [R_CHP_KOA_L1_6W0_8H0_45]  34.4 35.8 180 top
R180  -  [R_CHP_KOA_L1_6W0_8H0_45]  16.9 18.55 0 top
R181  -  [R_CHP_KOA_L1_6W0_8H0_45]  18.9 16.9 90 top
R182  -  [R_CHP_KOA_L1_6W0_8H0_45]  12.35 16.55 90 top
R183  -  [R_CHP_KOA_L1_6W0_8H0_45]  8.6 19.5 0 top
R184  -  [R_CHP_KOA_L1_6W0_8H0_45]  13.85 5.2 180 bottom
R187  -  [R_CHP_KOA_L1_6W0_8H0_45]  54.1 55.9 0 top
R188  -  [R_CHP_KOA_L1_6W0_8H0_45]  30.05 4.1 270 top
TP11  -  [TPAD_P_C2_0_RP0_05_MN]  64.9 49 180 top
TP12  -  [TPAD_P_C2_0_RP0_05_MN]  50.5 49.25 0 top
TP14  -  [TPAD_P_C2_0_RP0_05_MN]  70.65 43.7 90 top
TP16  -  [TPAD_P_C2_0_RP0_05_MN]  43.4 8.6 270 top
TP17  -  [TPAD_P_C2_0_RP0_05_MN]  83.15 11.85 180 top
TP19  -  [TPAD_P_C2_0_RP0_05_MN]  43.4 6 180 top
TP30  -  [TPAD_P_C1_0_RP0_05_MN]  38.45 39.85 180 top
TP32  -  [TPAD_P_C1_0_RP0_05_MN]  44.45 41.8 180 top
TP35  -  [TPAD_P_C1_0_RP0_05_MN]  82.3 3.35 180 top
TP37  -  [TPAD_P_C1_0_RP0_05_MN]  82.3 6.1 90 top
TP39  -  [TPAD_P_C2_0_RP0_05_MN]  27.3 57.75 0 top
TP40  -  [TPAD_P_C2_0_RP0_05_MN]  54.25 7.8 270 top
TP41  -  [TPAD_P_C2_0_RP0_05_MN]  9.9 40 0 top
TP42  -  [TPAD_P_C2_0_RP0_05_MN]  6.15 14.55 180 top
TP43  -  [TPAD_P_C2_0_RP0_05_MN]  54.3 49.4 270 top
TP44  -  [TPAD_P_C2_0_RP0_05_MN]  65.75 16.9 90 top
TP45  -  [TPAD_P_C2_0_RP0_05_MN]  66.75 38.95 0 top
TP46  -  [TPAD_P_C2_0_RP0_05_MN]  66.75 36.35 270 top
TP47  -  [TPAD_P_C2_0_RP0_05_MN]  25.05 16.7 90 top
TP48  -  [TPAD_P_C2_0_RP0_05_MN]  22.45 16.7 0 top

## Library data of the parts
C24 C28 C69 C70 C72-C74 C76 C79 C80 C82-C85 C91-C94 C96 C98 C100 C103-C106 C108 C110 C112-C115 C117-C119 C122 C123 C126 C127 C133-C135 C137-C139 C142 C143 C146 C147 = GCJ188R71H104KA12D
C35 C40 C54 C59 C71 C81 C124 C144 = C1608X5R1H105K080DB
C37 C38 C57 C58 C95 C107 C159 C160 = GRM21BZ71H475KE15L
C39 C47 C48 C56 C66 C67 = MSASU168SB7474KTNB25
C75 C77 C78 C86-C88 = 06035C680KAT2A
C89 C101 = KGM15ACG2A121KT: alternate symbols: (T:C_CHP_AVX_L1_6W0_8H0_9;B:C_CHP_AVX_L1_6W0_8H0_9,C89_C_CHP_AVX_L1_6W0_8H0_9,C101_C_CHP_AVX_L1_6W0_8H0_9)
C90 C97 C102 C109 C153 C154 C156 C157 = GRM21BR61H106KE43L
C99 C111 = 06035A200KAT2A
C116 C120 C121 C131 C136 C140 C141 C151 = GCD188R71H103KA01D
C128 C148 = 06035C100KAT2A
C130 C132 C150 C152 = C0603C102K5RACTU
C155 C158 = GCM188R71H102KA37D
CN2 CN3 = PM-61-9P
D24 D25 D40 D41 = CEZ5V6,L3F
D26-D28 D33-D35 = CRF03A,LQ(M
D29 D36 = CRZ10(T5L,TEM,Q)
D30 D37 = CUS05F30,H3F(T
D31 D32 D38 D39 = CRS04(TE85L,Q,M)
IC7 IC11 IC23 IC29 IC53 IC65 = TC7SZ04AFS,L3J
IC14 IC18 = S1213B00HV5T2U7
IC15 IC19 = TLV709A01DBVR
IC17 IC21 = TCR1HF50B,LM(CT
IC22 IC25 IC26 IC28 IC31 IC32 IC36 IC37 IC40 IC41 IC43-IC45 IC48 IC54 IC56 IC57 IC60 = TC7PZ14FU,LJ(CT
IC24 IC30 = TC75S57FU(TE85L,F)
IC27 IC33 IC42 IC49 IC55 IC61 = TC7WZ00FK,LJ(CT
IC34 IC38 IC46 IC47 IC58 IC59 = TC7WZ08FK,LJ(CT
IC35 IC39 = UCC27301ADRCR
IC50 IC63 = LTC1440IMS8
IC51 IC64 = LM393BIDDFR
P4 P5 P7 P11 P12 = ITNS-TH1.7-P_C2.2-RP0.05
Q7 Q10 Q11 Q14 Q22 Q23 Q28 Q29 = 2SC5658T2LR
Q8 Q12 Q24 Q25 Q30 Q31 = SSM3K15AFS,LF(T
Q9 Q13 = SSM3K318R,LF(T
Q15-Q20 = SSM6K804R,LF
Q21 Q27 = HN4A56JU
R27 R48 = RK73H1JTTD2003F
R28 R49 R85 R105 = RK73H1JTTD2001F: alternate symbols: (T:R_CHP_KOA_L1_6W0_8H0_45;B:R_CHP_KOA_L1_6W0_8H0_45,R105_R_CHP_KOA_L1_6W0_8H0_45,R85_R_CHP_KOA_L1_6W0_8H0_45)
R30 R34 R51 R55 = RK73H1JTTD1004F
R31 R52 = RK73H1JTTD4704F
R33 R54 = RK73H1JTTD2002F
R35 R56 = RK73H1JTTD3304F
R65 R73-R75 R83 R84 R89 R109 = RK73B1JTTD103J
R66 R69 R71 R76 R79 R81 = RK73B1JTTD512J
R67 R70 R77 R80 = RK73B1JTTD473J
R68 R78 = RK73B1JTTD471J
R72 R82 R94-R96 R100-R102 R114-R116 R120-R122 = RK73B1JTTD100J
R86 R106 = RK73H1JTTD2400F: alternate symbols: (T:R_CHP_KOA_L1_6W0_8H0_45;B:R_CHP_KOA_L1_6W0_8H0_45,R106_R_CHP_KOA_L1_6W0_8H0_45,R86_R_CHP_KOA_L1_6W0_8H0_45)
R87 R90 R103 R107 R110 R123 R177 R182 = RK73Z1JTTD: alternate symbols: (R177_R_CHP_KOA_L1_6W0_8H0_45,R182_R_CHP_KOA_L1_6W0_8H0_45)
R88 R91 R92 R108 R111 R112 = LTR10EZPF1R50
R93 R97 R98 R113 R117 R118 = LTR10EZPF9R10
R99 R119 = RT0603BRC07500RL
R104 R124 = RK73H1JTTD20R0F
R125 R150 = RK73H1JTTD4302F
R126 R127 R137 R139 R151 R152 R162 R164 = RK73B1JTTD303J
R128 R153 R187 R188 = RK73H1JTTD1003F
R129 R154 = RK73H1JTTD1202F
R130 R155 = RK73H1JTTD2201F
R131 R156 = RK73H1JTTD1001F: alternate symbols: (T:R_CHP_KOA_L1_6W0_8H0_45,R131_R_CHP_KOA_L1_6W0_8H0_45;B:R_CHP_KOA_L1_6W0_8H0_45,R156_R_CHP_KOA_L1_6W0_8H0_45)
R132 R157 = RK73H1JTTD8201F
R133 R158 = RK73H1JTTD1002F: alternate symbols: (T:R_CHP_KOA_L1_6W0_8H0_45,R133_R_CHP_KOA_L1_6W0_8H0_45;B:R_CHP_KOA_L1_6W0_8H0_45,R158_R_CHP_KOA_L1_6W0_8H0_45)
R134 R140 R159 R165 = RK73H1JTTD2702F
R135 R160 = RK73H1JTTD3301F
R136 R138 R143 R161 R163 R168 R178 R179 R183 R184 = RK73B1JTTD102J
R142 R167 = RK73H1JTTD3001F
R144 R169 = RK73B1JTTD472J
R146 R171 = RK73H1JTTD1502F
R147 R172 = RK73H1JTTD1802F
R148 R173 = RC0603FR-072M4L
R175 R176 R180 R181 = RK73B1JTTD221J
TP11 TP12 TP14 TP16 TP17 TP19 TP39-TP48 = TPAD-P_C2.0-RP0.05-MN
TP30 TP32 TP35 TP37 = TPAD-P_C1.0-RP0.05-MN

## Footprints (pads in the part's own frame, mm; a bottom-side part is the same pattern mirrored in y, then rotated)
C_CHP_AVX_L1_6W0_8H0_9
  rect 0.9x0.95 smd: 1(-0.9,0) 2(0.9,0)
C_CHP_AVX_L1_6W0_81H0_9
  rect 0.8x0.75 smd: 1(-0.75,0) 2(0.75,0)
C_CHP_KEMET_L1_6W0_8H0_8
  rect 1.15x1.1 smd: 1(-0.9,0) 2(0.9,0)
C_CHP_MURATA_L1_6W0_8H0_8A
  rect 0.65x0.7 smd: 1(-0.675,0) 2(0.675,0)
C_CHP_MURATA_L2_0W1_25H1_25
  rect 0.7x1.3 smd: 1(-0.95,0) 2(0.95,0)
C_CHP_TDK_L1_6W0_8H0_8
  rect 0.7x0.7 smd: 1(-0.7,0) 2(0.7,0)
C_CHP_TYYDN_L1_6W0_8H0_8A
  rect 0.7x0.825 smd: 1(-0.738,0) 2(0.738,0)
D_SMD_TSB_K_2_A_1_L1_7W1_25H0_9
  rect 0.8x0.9 smd: 1(1.15,0) 2(-1.15,0)
D_SMD_TSB_K_2_A_1_L2_6W1_6H0_98
  rect 1.2x1.2 smd: 1(1.4,0) 2(-1.4,0)
FET_SMD_TSB_D_1_2_5_6_G_3_S_4_L2_9W2_2H0_8_RP0_05
  rect 0.62x0.7 smd: 1(-0.95,-1.25) 2(0,-1.25) 3(0.95,-1.25) 4(0.95,1.25) 5(0,1.25) 6(-0.95,1.25)
FET_SMD_TSB_G_1_S_2_D_3_L1_6W0_8H0_75
  rect 0.6x0.6 smd: 1(-0.5,-0.7) 2(0.5,-0.7) 3(0,0.7)
FET_SMD_TSB_L2_9W1_8H0_8
  rect 0.8x0.9 smd: 1(-0.95,-1.05) 2(0.95,-1.05) 3(0,1.05)
IC_DDF_TI_L2_9W1_6H1_1_P0_65
  rect 0.45x1.05 smd: 1(-0.975,-1.3) 2(-0.325,-1.3) 3(0.325,-1.3) 4(0.975,-1.3) 5(0.975,1.3) 6(0.325,1.3) 7(-0.325,1.3) 8(-0.975,1.3)
IC_MS8_LINEAR_L3_0W3_0H1_1_P0_65
  rect 0.42x0.889 smd: 1(-0.975,-2.171) 2(-0.325,-2.171) 3(0.325,-2.171) 4(0.975,-2.171) 5(0.975,2.171) 6(0.325,2.171) 7(-0.325,2.171) 8(-0.975,2.171)
IC_SC74A_TSB_L2_9W1_6H1_15_RP0_05
  rect 0.8x1 smd: 1(-0.95,-1.2) 3(0.95,-1.2) 4(0.95,1.2) 5(-0.95,1.2)
  rect 0.6x1 smd: 2(0,-1.2)
IC_SC88A_TSB_L2_0W1_25H0_95_RP0_05
  rect 0.4x0.8 smd: 1(-0.65,-0.95) 2(0,-0.95) 3(0.65,-0.95) 4(0.65,0.95) 5(-0.65,0.95)
IC_SMD_5_TSB_L1_0W0_8H0_48_RCNT
  rect 0.2x0.2 smd: 1(-0.35,-0.425) 2(0,-0.425) 3(0.35,-0.425) 4(0.35,0.425) 5(-0.35,0.425)
IC_SON_10S1_TI_L3_1W3_1H1_0_RP0_05_2
  rect 0.24x0.6 smd: 1(-1,-1.4) 2(-0.5,-1.4) 3(0,-1.4) 4(0.5,-1.4) 5(1,-1.4) 6(1,1.4) 7(0.5,1.4) 8(0,1.4) 9(-0.5,1.4) 10(-1,1.4)
  custom 0.412x0.412 smd: 11(0,0)
IC_SOP_5_TI_L3_05W1_75H1_45
  rect 0.6x1.1 smd: 1(-0.95,-1.3) 2(0,-1.3) 3(0.95,-1.3) 4(0.95,1.3) 5(-0.95,1.3)
IC_SOP_6_TSB_L2_0W1_25H0_95_RP0_05
  rect 0.4x0.8 smd: 1(-0.65,-0.95) 2(0,-0.95) 3(0.65,-0.95) 4(0.65,0.95) 5(0,0.95) 6(-0.65,0.95)
IC_SOP_8_TSB_L2_0W2_3H0_75_P0_5_RP0_05
  rect 0.3x0.7 smd: 1(-0.75,-1.35) 2(-0.25,-1.35) 3(0.25,-1.35) 4(0.75,-1.35) 5(0.75,1.35) 6(0.25,1.35) 7(-0.25,1.35) 8(-0.75,1.35)
ITNS_TH1_7_P_C2_2_RP0_05
  round 2.2 hole 1.7: 1(0,0)
PM_61_9P
  round 1.3 hole 0.8: 1(0,0) 2(2.54,0) 3(5.08,0) 4(7.62,0) 5(10.16,0) 6(12.7,0) 7(15.24,0) 8(17.78,0) 9(20.32,0)
R_CHP_KOA_L1_6W0_8H0_45
  rect 0.5x0.6 smd: 1(-0.75,0) 2(0.75,0)
R_CHP_ROHM_L2_0W1_2H0_55
  rect 2x1.1 smd: 1(0,-0.8) 2(0,0.8)
R_CHP_YAGEO_L1_6W0_8H0_45
  rect 0.9x0.8 smd: 1(-0.85,0) 2(0.85,0)
REG_TO_252_5S_A_ABLIC_L6_5W4_7H1_4
  rect 0.8x1.5 smd: 1(-2.54,-3.3) 2(-1.27,-3.3) 4(1.27,-3.3) 5(2.54,-3.3)
  rect 6x3.6 smd: 3(0,1.25)
TPAD_P_C1_0_RP0_05_MN
  round 1 smd: 1(0,0)
TPAD_P_C2_0_RP0_05_MN
  round 2 smd: 1(0,0)
TR_SMD_3_TSB_B_1_E_2_C_3_L1_2W0_8H0_5
  rect 0.4x0.45 smd: 1(-0.4,-0.575) 2(0.4,-0.575)
  rect 0.5x0.45 smd: 3(0,0.575)
TR_USV_TSB_L2_0W1_25H1_1
  rect 0.4x0.8 smd: 1(-0.65,-0.95) 2(0,-0.95) 3(0.65,-0.95) 4(0.65,0.95) 5(-0.65,0.95)
ZD_SMD_TSB_K_1_A_2_L1_2W0_8H0_6
  rect 0.6x0.8 smd: 1(-0.85,0) 2(0.85,0)

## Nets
VCC20_A: C37.2 C38.2 C39.2 C90.2 C91.2 C116.2 C127.2 C153.2 C154.2 D31.2 IC14.5 IC15.1 IC51.8 Q15.1 Q15.2 Q15.5 Q15.6 R27.2 R125.2 R126.2 R127.2 R128.2 R129.2 R175.2 R176.2 TP11.1
VCC20_B: C56.2 C57.2 C58.2 C102.2 C103.2 C136.2 C147.2 C156.2 C157.2 D38.2 IC18.5 IC19.1 IC64.8 Q18.1 Q18.2 Q18.5 Q18.6 R48.2 R150.2 R151.2 R152.2 R153.2 R154.2 R180.2 R181.2 TP16.1
VEE_A: C24.2 C39.1 C40.1 C47.1 C48.1 C69.1 C70.1 C71.1 C72.1 C73.1 C74.1 C75.1 C76.1 C77.1 C78.1 C93.1 C95.1 C96.1 C97.1 C98.1 C99.1 C100.1 C113.1 C114.2 C115.2 C117.1 C118.1 C119.2 C122.2 C123.1 C124.2 C126.1 C127.1 C128.1 C130.1 C131.1 C132.1 C155.2 CN2.5 CN2.6 D24.2 D32.1 IC7.2 IC15.2 IC17.2 IC22.2 IC22.3 IC23.2 IC24.2 IC25.2 IC26.2 IC26.3 IC27.4 IC27.5 IC27.6 IC34.4 IC35.9 IC35.11 IC36.2 IC37.2 IC42.4 IC43.2 IC44.2 IC45.2 IC46.4 IC47.4 IC48.2 IC49.4 IC50.1 IC50.2 IC51.4 IC53.2 Q8.2 Q9.2 Q10.2 Q16.4 Q17.4 Q24.2 Q25.2 R34.1 R71.1 R73.1 R74.1 R147.1 R148.1 R187.1
VEE_B: C28.2 C56.1 C59.1 C66.1 C67.1 C79.1 C80.1 C81.1 C82.1 C83.1 C84.1 C85.1 C86.1 C87.1 C88.1 C105.1 C107.1 C108.1 C109.1 C110.1 C111.1 C112.1 C133.1 C134.2 C135.2 C137.1 C138.1 C139.2 C142.2 C143.1 C144.2 C146.1 C147.1 C148.1 C150.1 C151.1 C152.1 C158.2 CN3.5 CN3.6 D25.2 D39.1 IC11.2 IC19.2 IC21.2 IC28.2 IC28.3 IC29.2 IC30.2 IC31.2 IC32.2 IC32.3 IC33.4 IC33.5 IC33.6 IC38.4 IC39.9 IC39.11 IC40.2 IC41.2 IC54.2 IC55.4 IC56.2 IC57.2 IC58.4 IC59.4 IC60.2 IC61.4 IC63.1 IC63.2 IC64.4 IC65.2 Q12.2 Q13.2 Q14.2 Q19.4 Q20.4 Q30.2 Q31.2 R55.1 R81.1 R83.1 R84.1 R172.1 R173.1 R188.1
VIN_A: IC36.1 IC44.3 IC47.7 R136.2
VIN_B: IC40.1 IC56.3 IC59.7 R161.2
DESAT_A: C89.2 D29.2 D30.2 IC51.2 Q22.3 R85.1 R87.2 R177.1 TP41.1
DESAT_B: C101.2 D36.2 D37.2 IC64.2 Q28.3 R105.1 R107.2 R182.1 TP42.1
FAULT_2_A: CN2.9 IC53.4
FAULT_2_B: CN3.9 IC65.4
GCLP_EN_A: IC25.1 IC27.2 IC46.3
GCLP_EN_B: IC31.1 IC33.2 IC58.3
IN2_N_A: CN2.8 IC7.1 R187.2
IN2_N_B: CN3.8 IC11.1 R188.2
PRED_EN_A: C155.1 IC35.6 IC44.1 IC46.6 IC47.6 IC49.6 IC49.7
PRED_EN_B: C158.1 IC39.6 IC56.1 IC58.6 IC59.6 IC61.6 IC61.7
SIG00038: IC15.3
SIG00039: IC17.4
SIG00045: R27.1 R28.2
SIG00046: IC14.4 R28.1 R33.2
SIG00047: IC15.4 R30.1 R34.2
SIG00048: R30.2 R35.1
SIG00049: R31.1 R35.2
SIG00059: IC19.3
SIG00060: IC21.4
SIG00067: IC18.4 R49.1 R54.2
SIG00068: IC19.4 R51.1 R55.2
SIG00069: R51.2 R56.1
SIG00070: R52.1 R56.2
SIG00080: C77.2 IC25.3 R69.2
SIG00081: IC25.6 R69.1
SIG00082: IC26.6 Q8.1
SIG00083: IC25.4 IC26.1
SIG00084: IC26.4
SIG00085: C75.2 IC24.3 R68.1 R73.2
SIG00086: IC24.1 R66.1 R71.2
SIG00087: IC24.4 R70.2
SIG00088: Q10.1 R70.1
SIG00089: C78.2 IC22.1 Q10.3 R67.1
SIG00090: IC22.6 IC27.1
SIG00091: IC22.4
SIG00092: IC23.1 IC27.7
SIG00093: IC23.3
SIG00094: IC27.3
SIG00095: IC23.4 R72.1
SIG00096: D24.1 Q7.1 Q8.3 R65.1
SIG00097: Q9.1 R72.2 R74.2 TP39.1
SIG00098: Q7.2 R68.2
SIG00099: C87.2 IC31.3 R79.2
SIG00100: IC31.6 R79.1
SIG00101: IC31.4 IC32.1
SIG00102: IC32.6 Q12.1
SIG00103: IC32.4
SIG00104: C86.2 IC30.3 R78.1 R83.2
SIG00105: IC30.1 R76.1 R81.2
SIG00106: IC30.4 R80.2
SIG00107: Q14.1 R80.1
SIG00108: C88.2 IC28.1 Q14.3 R77.1
SIG00109: IC28.6 IC33.1
SIG00110: IC28.4
SIG00111: IC29.1 IC33.7
SIG00112: IC29.3
SIG00113: IC33.3
SIG00114: IC29.4 R82.1
SIG00115: D25.1 Q11.1 Q12.3 R75.1
SIG00116: Q13.1 R82.2 R84.2 TP40.1
SIG00117: Q11.2 R78.2
SIG00118: IC34.2 IC36.3 IC36.6 R99.1
SIG00119: IC34.6 IC36.4
SIG00120: C99.2 IC37.1 R99.2
SIG00121: IC34.1 IC37.4
SIG00122: IC34.3 IC35.7 TP30.1
SIG00123: IC34.5 IC37.3 IC37.6
SIG00124: IC34.7 IC35.8 TP32.1
SIG00126: IC35.4 R90.1
SIG00127: C94.2 IC35.3
SIG00128: IC35.2
SIG00129: IC35.10 R103.1
SIG00130: Q16.3 R103.2
SIG00131: Q15.4 R88.1 R91.1 R92.1
SIG00132: Q16.1 Q16.2 Q16.5 Q16.6 R93.1 R97.1 R98.1
SIG00133: Q17.1 Q17.2 Q17.5 Q17.6 R100.1 R101.1 R102.1
SIG00134: Q17.3 R104.2
SIG00135: R94.1 R95.1 R96.1 R100.2 R101.2 R102.2
SIG00136: Q15.3 R90.2
SIG00137: R85.2 R86.1
SIG00138: D26.1 R86.2
SIG00139: D26.2 D27.1
SIG00140: D27.2 D28.1
SIG00141: D28.2 P7.1
SIG00142: IC38.2 IC40.3 IC40.6 R119.1
SIG00143: IC38.1 IC41.4
SIG00144: IC38.3 IC39.7 TP35.1
SIG00145: IC38.6 IC40.4
SIG00146: C111.2 IC41.1 R119.2
SIG00147: IC38.5 IC41.3 IC41.6
SIG00148: IC38.7 IC39.8 TP37.1
SIG00150: IC39.10 R123.1
SIG00151: IC39.4 R110.1
SIG00152: C106.2 IC39.3
SIG00153: IC39.2
SIG00154: Q19.3 R123.2
SIG00155: Q18.3 R110.2
SIG00156: Q18.4 R108.1 R111.1 R112.1
SIG00157: R105.2 R106.1
SIG00158: Q19.1 Q19.2 Q19.5 Q19.6 R113.1 R117.1 R118.1
SIG00159: Q20.1 Q20.2 Q20.5 Q20.6 R120.1 R121.1 R122.1
SIG00160: Q20.3 R124.2
SIG00161: R114.1 R115.1 R116.1 R120.2 R121.2 R122.2
SIG00162: D33.1 R106.2
SIG00163: D33.2 D34.1
SIG00164: D34.2 D35.1
SIG00166: Q22.1 R126.1 R178.2
SIG00167: C116.1 Q21.2 Q21.5 R131.2
SIG00168: R131.1 R133.2
SIG00169: C120.2 IC51.3 R129.1 R132.2
SIG00170: Q23.1 R127.1 R179.2
SIG00171: D40.2 Q23.3 R135.2
SIG00172: C121.2 D40.1 IC51.6 R128.1
SIG00173: R125.1 R130.2
SIG00174: IC51.5 R130.1 R134.2
SIG00175: Q24.1 R136.1
SIG00176: C128.2 IC48.1 IC51.1 R137.1
SIG00177: Q25.1 R138.1
SIG00178: IC51.7 R143.2
SIG00179: C130.2 IC43.1 R139.1 R143.1
SIG00180: R140.1 R142.2
SIG00181: C131.2 IC50.3 R142.1 R147.2
SIG00182: IC50.4 IC50.6 R146.2
SIG00183: IC50.5 R146.1 R148.2
SIG00184: IC49.2 IC49.3
SIG00185: IC50.8 R144.2
SIG00186: C132.2 IC45.1 R144.1
SIG00187: IC47.3 IC53.1
SIG00188: IC53.3
SIG00190: IC7.3
SIG00190_2030911: IC11.3
SIG00191: IC43.3 IC43.6 R138.2
SIG00192: IC43.4 IC46.1
SIG00193: IC45.3 IC45.6
SIG00194: IC45.4 IC46.2 IC49.1
SIG00195: IC48.3 IC48.6
SIG00196: IC42.2 IC42.3
SIG00197: IC42.6 IC42.7 IC47.1 IC47.5
SIG00198: IC42.5 IC46.7 TP45.1
SIG00199: IC48.4 IC49.5 TP46.1
SIG00200: IC44.4 IC46.5
SIG00201: IC61.2 IC61.3
SIG00202: IC55.5 IC58.7 TP47.1
SIG00203: Q28.1 R151.1 R183.2
SIG00205: R156.1 R158.2
SIG00206: C140.2 IC64.3 R154.1 R157.2
SIG00207: Q29.1 R152.1 R184.2
SIG00208: D41.2 Q29.3 R160.2
SIG00209: C141.2 D41.1 IC64.6 R153.1
SIG00210: R150.1 R155.2
SIG00211: IC64.5 R155.1 R159.2
SIG00212: Q30.1 R161.1
SIG00214: Q31.1 R163.1
SIG00215: IC64.7 R168.2
SIG00216: C150.2 IC54.1 R164.1 R168.1
SIG00217: R165.1 R167.2
SIG00218: C151.2 IC63.3 R167.1 R172.2
SIG00219: IC63.4 IC63.6 R171.2
SIG00220: IC63.5 R171.1 R173.2
SIG00221: IC60.4 IC61.5 TP48.1
SIG00222: IC63.8 R169.2
SIG00223: C152.2 IC57.1 R169.1
SIG00224: IC59.3 IC65.1
SIG00225: IC65.3
SIG00228: IC54.3 IC54.6 R163.2
SIG00229: IC54.4 IC58.1
SIG00230: IC55.2 IC55.3
SIG00231: IC55.6 IC55.7 IC59.1 IC59.5
SIG00232: IC56.4 IC58.5
SIG00233: IC57.3 IC57.6
SIG00234: IC57.4 IC58.2 IC61.1
SIG00235: IC60.3 IC60.6
STO_VMOS_A: IC44.6 R104.1 TP43.1
STO_VMOS_B: IC56.6 R124.1 TP44.1
VE_A: C35.1 C37.1 C38.1 C47.2 C89.1 C90.1 C91.1 C92.2 C97.2 C98.2 C120.1 C121.1 C153.1 C154.1 C159.1 CN2.3 CN2.4 D29.1 D30.1 D35.2 IC14.3 IC17.1 IC17.3 P5.1 Q22.2 Q23.2 R33.1 R87.1 R89.2 R132.1 R133.1 R134.1 R135.1
VE_B: C54.1 C57.1 C58.1 C66.2 C101.1 C102.1 C103.1 C104.2 C109.2 C110.2 C140.1 C141.1 C156.1 C157.1 C160.1 CN3.3 CN3.4 D36.1 D37.1 IC18.3 IC21.1 IC21.3 P12.1 Q28.2 Q29.2 R54.1 R107.1 R109.2 R157.1 R158.1 R159.1 R160.1
VGATE_A: C92.1 C94.1 D31.1 D32.2 IC35.5 P4.1 Q7.3 Q9.3 R65.2 R88.2 R89.1 R91.2 R92.2 R93.2 R94.2 R95.2 R96.2 R97.2 R98.2
VGATE_B: C104.1 C106.1 D38.1 D39.2 IC39.5 P11.1 Q11.3 Q13.3 R75.2 R108.2 R109.1 R111.2 R112.2 R113.2 R114.2 R115.2 R116.2 R117.2 R118.2
VGD_A: C40.2 C95.2 IC15.5 IC35.1 R31.2 TP12.1
VGD_B: C59.2 C107.2 IC19.5 IC39.1 R52.2 TP17.1
VL_A: C24.1 C48.2 C69.2 C70.2 C71.2 C72.2 C73.2 C74.2 C76.2 C93.2 C96.2 C100.2 C113.2 C114.1 C115.1 C117.2 C118.2 C119.1 C122.1 C123.2 C124.1 C126.2 CN2.7 IC7.5 IC17.5 IC22.5 IC23.5 IC24.5 IC25.5 IC26.5 IC27.8 IC34.8 IC36.5 IC37.5 IC42.8 IC43.5 IC44.5 IC45.5 IC46.8 IC47.8 IC48.5 IC49.8 IC50.7 IC53.5 R66.2 R67.2 R137.2 R139.2 R140.2 TP14.1
VL_B: C28.1 C67.2 C79.2 C80.2 C81.2 C82.2 C83.2 C84.2 C85.2 C105.2 C108.2 C112.2 C133.2 C134.1 C135.1 C137.2 C138.2 C139.1 C142.1 C143.2 C144.1 C146.2 CN3.7 IC11.5 IC21.5 IC28.5 IC29.5 IC30.5 IC31.5 IC32.5 IC33.8 IC38.8 IC40.5 IC41.5 IC54.5 IC55.8 IC56.5 IC57.5 IC58.8 IC59.8 IC60.5 IC61.8 IC63.7 IC65.5 R76.2 R77.2 R162.2 R164.2 R165.2 TP19.1
N03856: C35.2 C159.2 CN2.1 CN2.2 IC14.1 IC14.2
N502328: C54.2 C160.2 CN3.1 CN3.2 IC18.1 IC18.2
N679544: R48.1 R49.2
N855499: IC7.4 IC42.1 IC47.2
N871149: IC11.4 IC55.1 IC59.2
N871259: C136.1 Q27.2 Q27.5 R156.2
N872651: C148.2 IC60.1 IC64.1 R162.1
N1924743: Q21.1 R176.1
N1924835: Q21.3 R175.1
N1941594: Q24.3 R178.1
N1941665: Q25.3 R179.1
N1965883: Q27.1 R181.1
N1966369: Q27.3 R180.1
N1966980: Q21.4 R177.2
N1967040: Q27.4 R182.2
N1967770: Q31.3 R184.1
N1967776: Q30.3 R183.1

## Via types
v1: diameter 0.8, hole 0.4, TOP to BOTTOM, 299 vias
v2: diameter 0.6, hole 0.3, TOP to BOTTOM, 114 vias

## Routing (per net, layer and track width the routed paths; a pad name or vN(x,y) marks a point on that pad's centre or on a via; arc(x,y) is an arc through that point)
VCC20_A: length 68.7
  TOP w0.5: R128.2 32.45,36.55 32.05,36.95 v1(30.85,36.95) 29.9,36.95 R127.2 ; R176.2 17.68,41.55 17.6,41.48 17.52,41.55 R175.2 15.95,41.85 v1(15.95,42.65) ; IC15.1 47.9,51.59 C39.2 ; R126.2 13.15,43.15 v1(13.1,43.75)
  CONDUCTIVE3 w1: 65.28,59.27 64.05,60.5 40.3,60.5 39.45,59.65 ; 18.05,48.75 18.05,50.15 26,58.1 27.68,58.1 ; 22.73,51.87 23.27,51.33
  BOTTOM w0.3: IC51.8 19.73,38.92 19.52,38.73 19.52,38.35 19.77,38.1 C127.2
  BOTTOM w0.5: C127.2 19.77,36.62 v1(20.1,36.3) ; R125.2 21.15,45.1 20.25,46 v1(18.45,46) 18.65,45.43 R129.2 ; R27.2 65.65,48.45
  BOTTOM w1: v1(25.2,49.4) 30.55,49.4 D31.2
  vias: v1(24.2,50.4) v1(24.2,49.4) v1(25.2,50.4) v1(29.2,58) v1(29.2,57) v1(30.2,58) v1(30.2,57) v1(49.65,56.35) v1(49.65,55.35) v1(50.65,56.35) v1(50.65,55.35) v1(65.7,47.45) v1(65.7,46.45) v1(66.7,47.45) v1(66.7,46.45)
VCC20_B: length 39.2
  TOP w0.3: C147.2 11.15,9.53 10.88,9.8 10.6,9.8 10.38,9.57 IC64.8
  TOP w0.5: R153.2 v1(9.55,2.75) ; R181.2 18.55,17.65 R180.2 v1(17.65,19.55) ; v1(12.7,8.35) 12.36,8.84 11.85,9.35 C147.2 ; v1(6.45,19.55) 6.9,19.15 R151.2 ; IC19.1 80.75,18 80.75,18.5 81.14,18.89 C56.2
  TOP w0.8: IC18.5 41.15,10.5
  CONDUCTIVE3 w0.3: 36.85,4.15 36.85,2.35
  CONDUCTIVE3 w0.5: 31.85,4.15 31.85,2.45 ; 34.4,4 34.4,2.6
  CONDUCTIVE3 w1: 59.73,6.03 60.55,6.85 65.31,6.85 ; 43.45,1.5 51,1.5
  BOTTOM w0.5: R154.2 v1(12.7,8.35) ; R152.2 v1(14.6,2.75) ; R48.2 v1(41.65,8.65) ; C136.2 12.8,17.77 v1(12.8,19.2) ; R150.2 8,12.05 v1(7.95,12.65)
  vias: v1(41.65,7.65) v1(41.65,6.65) v1(41.65,5.65) v1(55.25,3.45) v1(55.25,2.45) v1(56.25,3.45) v1(56.25,2.45) v1(69.65,10.15) v1(69.65,9.15) v1(70.65,10.15) v1(70.65,9.15)
VEE_A: length 197.8
  TOP w0.2: IC7.2 v1(54.25,54.4) IC53.2
  TOP w0.24: v1(43.85,49.05) 43.35,48.55 43.35,43.5 41.81,41.96 37.09,41.96 36.6,42.45 IC35.9 36.6,43.85 v1(36.85,44.35)
  TOP w0.25: IC43.2 58.4,41 58.25,41.15 57.27,41.15 57.05,40.92 56.4,40.92
  TOP w0.3: 58.92,51.6 58.92,49.19 58.69,48.95 IC47.4 ; IC26.2 26.65,45.1 26.45,44.9 26.45,44.45 ; C117.1 62.08,41.42 62.6,40.9 62.6,40.4 61.85,39.65 IC46.4 ; 56.4,36.92 56.62,37.15 58.05,37.15 58.3,36.9 IC48.2 ; 26.45,44.45 26.45,43.88 C69.1 ; 26.45,44.45 IC26.3 ; 59.4,46.08 58.62,46.08 58.15,46.55 57.7,46.55 57.4,46.85 IC44.2 ; IC50.1 76.67,39.17 ; 76.67,39.17 C126.1 ; 76.67,39.17 76.67,38.77 76.42,38.52 75.28,38.52 ; C93.1 43.9,38.5 44.58,37.83 IC34.4 ; IC42.4 61.75,43.75 62.12,44.12 C113.1 ; 61.92,38.2 61.92,35.77 61.7,35.55 IC49.4 ; C76.1 22.48,46.95 24.35,46.95 24.8,46.5 IC25.2 24.8,45.2 C77.1 ; IC37.2 48.52,38.5 48.3,38.73 46.75,38.73 C100.1 ; IC45.2 54.4,36.9 54.15,37.15 52.73,37.15 52.5,36.92 ; C74.1 53.62,44.48 53.25,44.85 IC24.2
  TOP w0.5: v1(47.48,35.42) 48.52,35.42 48.98,35.88 C99.1 ; v1(54.25,51.65) 54.2,52.25 C124.2 ; C100.1 46.35,38.6 46.12,38.37 v1(45.62,38.02) ; C76.1 v1(21.3,47.12) 18.95,44.77 18.95,44.45 Q24.2 ; v1(40.92,38.52) 41.52,38.5 C93.1 ; 56.4,40.92 v1(55.17,40.92) ; v1(37.4,38.6) C75.1 36,38.45 R73.1 34.75,37.7 v1(35.25,37.2) Q25.2 ; v1(27,42.15) 27.12,42.27 C69.1 ; C113.1 61.4,46.4 60.95,46.85 v1(60.95,47.45) 60.25,47.45 59.4,46.6 59.4,46.08 ; 57,52.92 57,52.75 v1(57.8,51.95) 58.15,51.6 58.92,51.6 ; C117.1 v1(61.1,42.3) ; C126.1 74.9,40.6 ; 29.35,43.2 D24.2 30.15,44.25 Q8.2 ; 61.92,38.2 v1(60.95,38.2) ; 52.5,36.92 v1(52.5,35.95) ; R187.1 53.25,55.9 v1(52.3,56.85) ; C74.1 v1(55.5,44.48) ; IC15.2 46.95,50.6 ; C155.2 33.5,44.65 ; 56.4,36.92 v1(56.4,35.95) ; C132.1 81.55,36.8 R148.1 v1(82.85,35.6)
  CONDUCTIVE3 w0.5: CN2.5 52.89,57.5 ; CN2.5 54.1,58.7 ; CN2.5 CN2.6 ; CN2.6 49.3,58.7 ; CN2.6 50.35,57.65
  CONDUCTIVE3 w1: 45.17,32 15.85,32 14.15,33.7 14.15,34.7
  BOTTOM w0.2: IC23.2 26.85,55
  BOTTOM w0.3: C96.1 48.65,37.73 47.62,37.73 47.42,37.52 IC36.2 ; C127.1 18.43,38.12 18.9,38.6 18.9,40.55 18.57,40.88 IC51.4 ; 30.23,44.55 IC22.3 ; 30.23,44.55 30.23,44.98 30.45,45.2 IC22.2 ; 30.23,44.55 C70.1 ; IC27.4 26.6,45.45 ; v1(37.4,38.6) 36.1,39.9 34.02,39.9 ; IC27.5 25.55,45.45 ; IC27.6 25.55,45.95 ; R34.1 49.7,49.2
  BOTTOM w0.5: R71.1 54.83,45.15 v1(55.5,44.48) ; v1(28,39.65) 28.55,39.65 28.9,39.3 C130.1 ; C71.1 28.15,50.92 C72.1 28.32,50.7 v1(29.2,50.7) ; Q9.2 33.4,54.65 32.6,53.85 R74.1 32,55.1 31.1,56 v1(27.3,56) ; C96.1 v1(50.55,38.4) ; C127.1 v1(16.8,37.5) C128.1 ; v1(26.4,47) 26.4,47.12 26.77,47.5 C73.1 ; v1(29.6,42.15) 30.23,42.77 C70.1 ; v1(35.35,44.35) 34.2,43.2 C78.1
  BOTTOM w0.8: v1(45.62,38.02) 45.05,38.02 44.55,37.52 44.55,36.3 45.42,35.42 v1(47.48,35.42)
  vias: v1(26.3,56) v1(26.3,55) v1(27.3,55) v1(40.55,43.35) v1(41.55,43.35) v1(43.85,50.05) v1(44.85,55.8) v1(44.85,54.8) v1(44.85,50.05) v1(44.85,49.05) v1(44.85,45.9) v1(44.85,44.9) v1(45.85,55.8) v1(45.85,54.8) v1(72.75,39.95) v1(72.75,38.95) v1(73.55,48.45) v1(73.55,47.45) v1(73.75,39.95) v1(73.75,38.95) v1(74.55,48.45) v1(74.55,47.45) v1(79.8,44.6) v1(80.8,44.6) v1(82.35,43.9) v1(83.35,43.9)
VEE_B: length 430.4
  TOP w0.15: C144.2 23.43,4.4 23.23,4.2 23.23,3.85 22.93,3.55 22.35,3.55 22.25,3.65 22.25,3.98 ; 83.65,3.24 83.65,7.5 83.48,7.67 ; v1(88.12,5.25) 88.12,4.67 86.38,2.92 85.21,2.92 ; v1(17.95,8.3) 16.1,8.3 v1(15.5,8.35) 15.9,8.75 15.9,13.2 16.3,13.6 v1(17.8,13.6) 17.25,13.05 17.25,11.4 18.7,9.95 v1(21,9.95)
  TOP w0.2: 28.25,3.73 28.25,3.33 27.95,3.02 26.4,3.02
  TOP w0.24: v1(77.25,9.85) 77,9.3 IC39.9 77,7.75 77.1,7.65 77.1,6.24 76.66,5.8 74.15,5.8 73.3,6.65 v1(70.65,6.65)
  TOP w0.3: IC30.2 58,16.7 57.75,16.45 57.75,15.55 58.12,15.18 C84.1 ; 50.65,13.75 49.98,13.75 C80.1 ; 50.65,13.75 IC28.3 ; 50.65,13.75 51.05,13.75 51.3,13.5 IC28.2 ; IC33.6 55.4,10.25 ; C88.1 49.52,17.07 Q14.2 ; v1(27.85,6.65) 28.19,6.16 29.5,4.85 R188.1 ; C137.1 21.45,11.15 21.73,10.88 22.6,10.88 23.02,10.45 24.81,10.45 24.95,10.59 24.95,11.32 ; IC57.2 29.4,13 29.6,12.8 30.43,12.8 30.95,13.32 31.8,13.32 ; IC56.2 29.4,8.15 29.65,7.9 30.4,7.9 30.93,8.43 C135.2 ; IC64.4 8.43,10.72 8.7,10.45 10.9,10.45 11.32,10.88 C147.1 ; IC40.2 85,4.43 85.38,4.05 86.45,4.05 87.05,4.65 C108.1 ; IC33.5 55.4,9.75 ; C111.1 87.75,10.5 87,11.25 IC41.2 87,12.9 86.8,13.1 85.92,13.1 85.7,12.88 C112.1 ; C138.1 21.85,6.45 22.75,5.55 24.71,5.55 24.95,5.79 24.95,6.42 ; IC33.4 54.4,9.75 ; C83.1 54.12,11.75
  TOP w0.5: 26.4,3.02 25.52,3.02 25.25,3.3 v1(25.25,4.4) C144.2 ; C111.1 87.75,9 v1(87.4,8.65) ; v1(52.9,12.5) 54.02,12.5 C83.1 ; R81.1 61.95,14.5 62.55,15.1 v1(62.55,17.35) C86.1 R83.1 ; v1(48.05,12.4) 48.05,12.9 48.33,13.18 C80.1 ; C135.2 v1(32.1,9.6) ; R55.1 77.05,20.15 ; R55.1 75.9,19.2 ; R55.1 78.2,19.2 ; 73.5,9.32 74.25,9.32 ; C137.1 20.35,12.03 ; C112.1 v1(85.05,11.7) ; C88.1 v1(49.4,18.2) ; C108.1 87.12,5.25 v1(88.12,5.25) ; C147.1 v1(11.85,12.05) ; 31.8,13.32 31.8,14.35 ; 79.75,16.9 IC19.2 79.75,19.36 C56.1 ; C66.1 49.6,5.74 49.6,7.62 v1(49.75,8.2) IC21.2 ; v1(58.15,13.4) 58.12,14 C84.1 ; C138.1 v1(20.65,7.1)
  CONDUCTIVE3 w0.4: 49.09,4.65 47.7,4.65 46.95,3.9
  CONDUCTIVE3 w1: v1(33.1,14.1) 30.7,14.1 ; 43.31,5.6 43.31,8.35 ; v1(25.25,4.4) 23.4,6.25 ; 61.13,11.7 69.84,11.7
  BOTTOM w0.15: 22.95,7.6 22.95,9.56 23.07,9.68 23.07,10.17 22.64,10.6 21.65,10.6 v1(21,9.95) 21.55,9.4 21.55,8 v1(20.65,7.1) 20.65,5.95 23.4,3.2 27.5,3.2 29.35,5.05 29.35,5.65 30.6,6.9 ; v1(32.1,9.6) 32.1,7.8 31.2,6.9 30.6,6.9 ; 88.4,2.4 88.5,2.4 91.4,5.3 91.4,10.45 85.5,16.35 v1(82.7,16.35) v1(82.7,17.35) v1(81.7,17.35) 77.15,17.35 v1(75.9,18.6) v1(75.9,19.6) v1(74.9,19.6) 71.25,19.6 68.95,21.9 62.2,21.9 59.9,19.6 v1(55.6,19.6) 54.55,20.65 40.95,20.65 v1(39.7,19.4) 38.85,18.55 38.85,16.05 34.67,11.88 30.12,11.88 28.77,10.53 28.77,9.43 28.05,8.7 27.65,8.7 27.3,8.35 27.3,8.13 ; 86.52,2.92 85.33,2.92 85.1,3.15 85.1,3.75 85.35,4 87.7,4 88.12,4.42 v1(88.12,5.25) 89.5,5.25 90.4,6.15 90.4,7.05 89.65,7.8 88.25,7.8 v1(87.4,8.65) 88.75,10 88.75,11.3 88.35,11.7 v1(85.05,11.7) ; 55.48,10.6 55.48,10 55.33,9.85 54.8,9.85 54.6,9.65 54.6,9.1 54.7,9 IC29.2 ; 30.6,6.9 29.52,7.97 29.52,9.97 30.68,11.12 34.99,11.12 41.45,17.59 v1(41.45,18.2) 42.85,19.6 52.4,19.6 v1(52.9,19.1) 53.5,18.5 60.25,18.5 62.7,20.95 67.6,20.95 v1(69.65,18.9) 72.7,15.85 77.95,15.85 80.9,12.9 80.9,11.81 ; v1(27.85,6.65) 28.55,5.95 28.55,5.4 27.55,4.4 v1(25.25,4.4) 24.45,4.4 23.45,5.4 23.45,6.42
  BOTTOM w0.3: 23.45,6.42 23.45,7.2 23.65,7.4 C133.1 ; C143.1 26.75,11.5 25.55,10.3 23.9,10.3 23.45,10.75 23.45,11.32 ; IC60.2 21.25,12.99 21.08,12.82 20.12,12.82 19.62,13.32 19,13.32 ; 51.7,15.8 51.7,16.25 51.9,16.45 IC32.3 ; 51.7,15.8 51.7,14.62 C79.1 ; 51.7,15.8 IC32.2 ; 86.4,6.22 85.62,6.22 85.05,6.8 83.9,6.8 83.15,6.05 IC38.4 ; C85.1 49.23,12.97 48.65,13.55 48.65,14.3 48.45,14.5 IC31.2 ; IC54.2 21.25,17.92 21.08,17.75 19.02,17.75 C134.2 ; C146.1 31.57,17.4 ; 31.57,17.4 IC63.1 ; 31.57,17.4 31.57,17.02 31.85,16.75 IC63.2
  BOTTOM w0.5: Q30.2 13.15,12.5 12.7,12.05 v1(11.85,12.05) ; 86.4,5.3 86.4,6.22 87.22,6.22 87.74,5.71 v1(88.12,5.25) ; R173.1 31.7,12.65 32.7,13.65 v1(33.1,14.1) ; C143.1 v1(27.75,12) ; 27.3,7.4 C133.1 26.5,6.5 ; 19,13.32 18.33,13.32 v1(17.8,13.6) ; v1(62.55,17.35) 61.65,16.45 D25.2 58.45,16.45 Q12.2 ; C148.1 15.5,9.35 v1(15.5,8.35) ; 56.35,10.6 55.48,10.6 55.48,11.97 C81.1 56.5,12 ; C87.1 v1(45.15,14.75) ; 35.75,19.9 C151.1 35.67,18.9 R172.1 ; R172.1 33.05,18.9 v1(32.75,19.2) 32.15,19.18 C146.1 31.57,20.15 ; R172.1 34.4,19.9 ; Q31.2 v1(17.95,8.3) ; C152.1 v1(24.85,18.52) ; Q13.2 61.3,7.3 60.6,8 R84.1 60.15,8.6 59.8,8.95 57.15,8.95 v1(56.85,8.65) ; C150.1 v1(15.6,19.55) ; C85.1 v1(48.05,12.4) ; C79.1 52.62,13.03 v1(52.9,12.5) ; v1(19.2,18.95) 19.2,17.98 C134.2
  BOTTOM w0.8: v1(55.85,8.65) v1(56.85,8.65)
  vias: v1(45.45,11.35) v1(45.45,10.35) v1(46.45,11.35) v1(46.45,10.35) v1(57.15,13.4) v1(67.55,17.35) v1(67.55,16.35) v1(69.65,7.65) v1(69.65,6.65) v1(70.65,7.65) v1(74.9,18.6) v1(75.75,9.85) v1(76.45,3.65) v1(76.45,2.45) v1(80.8,9.65) v1(80.8,8.65) v1(81.7,16.35) v1(81.8,9.65) v1(81.8,8.65) v1(84.05,2.4) v1(87.45,2.4) v1(92.6,19.6) v1(92.6,14.6) v1(92.6,9.6)
VIN_A: length 59.5
  TOP w0.3: v2(50.55,37.2) 51.25,37.9 51.25,39.75 54.8,43.3 56.75,43.3 v2(57.1,43.65) ; IC44.3 56.75,48.1 v2(57.1,48.45) 57.55,48.4 59,48.4 59.53,48.93 59.53,49.43 60.05,49.95 IC47.7 ; R136.2 21.85,43.35 24.8,40.4 v2(25.2,40.4)
  BOTTOM w0.3: v2(57.1,48.45) v2(57.1,43.65) ; v2(25.2,40.4) 28.9,40.4 34.65,34.65 48.55,34.65 50.55,36.65 v2(50.55,37.2) 49.88,37.2 48.7,36.02 48.27,36.02 48.08,36.23 48.08,36.92
VIN_B: length 117.4
  TOP w0.3: v2(85.65,3.45) 85,3.45 84.35,4.1 IC40.1 ; v2(27.85,7.9) 28.55,7.9 28.75,8.1 IC56.3 ; v2(16.5,12.3) 16.5,11.5 18.75,9.25 21.85,9.25 v2(22.55,9.95) 23.75,9.95 23.95,9.75 IC59.7
  BOTTOM w0.3: v2(85.65,3.45) 88.4,3.45 90.9,5.95 90.9,9.85 88.05,12.7 82,12.7 78.25,16.45 73.25,16.45 68.25,21.45 62.45,21.45 59.9,18.9 55,18.9 53.8,20.1 41.9,20.1 40.35,18.55 40.35,17.02 34.83,11.5 30.53,11.5 29.15,10.12 29.15,9.2 v2(27.85,7.9) 28.95,6.8 28.95,5.2 27.35,3.6 24.7,3.6 22.55,5.75 v2(22.55,9.95) ; R161.2 v2(16.5,12.3)
DESAT_A: length 6.7
  TOP w0.3: Q22.3 13.4,39.05 ; R177.1 13.35,37.9
  BOTTOM w0.3: 12.9,39.3 13.18,39.58 17.8,39.58
  vias: v1(7.65,38.05) v1(8.65,38.05) v1(9.65,38.05) v1(10.65,38.05)
DESAT_B: length 11.5
  TOP w0.3: IC64.2 9.72,12.97 9.25,13.45 7.55,13.45 7.1,13 ; Q28.3 8.9,15.05 ; R182.1 11.5,15.8
  TOP w0.5: TP42.1 4.25,14.55 ; TP42.1 v1(6.15,12.75) ; TP42.1 7.95,14.55
  vias: v1(4.15,13.75) v1(4.15,12.75) v1(5.15,12.75)
FAULT_2_A: length 12
  TOP w0.2: IC53.4 52.58,55.58
  TOP w0.3: CN2.9 44.33,57.1 51.05,57.1 52.58,55.58
FAULT_2_B: length 36.5
  TOP w0.2: IC65.4 v2(21.9,2.3)
  BOTTOM w0.3: CN3.9 52.3,4.42 50.4,4.42 47.72,7.1 44.5,7.1 42.25,4.85 31.7,4.85 28.5,1.65 22.55,1.65 v2(21.9,2.3)
GCLP_EN_A: length 50.7
  TOP w0.15: IC46.3 60.35,40.15 v2(59.9,40.1)
  TOP w0.3: IC25.1 24.15,45.7 23.95,45.5 v2(23.4,45.5)
  BOTTOM w0.15: 26.3,44.6 26.3,41.85 27.35,40.8 29.1,40.8 32,37.9 36.75,37.9 37.35,37.3 42.1,37.3 44.85,40.05 44.85,41.1 45.45,41.7 49.7,41.7 51.1,40.3 57.35,40.3 57.55,40.1 v2(59.9,40.1) ; 26.3,44.6 24.3,44.6 v2(23.4,45.5) ; 26.3,44.6 27.6,44.6 28.15,45.15 28.15,46.25 27.95,46.45 IC27.2
GCLP_EN_B: length 37.5
  TOP w0.3: v2(52.58,10.03) 52.58,10.43 52.9,10.75 IC33.2 ; 24.45,11.32 24.45,11.95 25.1,12.6 26.15,12.6 28.4,10.35 32.45,10.35 v2(33.2,9.6)
  BOTTOM w0.3: v2(33.2,9.6) 35.26,9.6 39.51,13.85 IC31.1 47.85,13.25 47.25,12.65 47.25,11.2 48.42,10.03 v2(52.58,10.03)
IN2_N_A: length 12.4
  TOP w0.2: IC7.1 55.08,55.67 R187.2
  TOP w0.3: R187.2 54.85,56.65 53.95,57.55 46.42,57.55 CN2.8
IN2_N_B: length 26.6
  TOP w0.15: 27.9,3.73 27.9,4.05 28,4.15 28.9,4.15 29.2,3.85 29.2,3.6 29.45,3.35 R188.2
  TOP w0.3: R188.2 v2(31.1,3.35)
  BOTTOM w0.3: v2(31.1,3.35) 32.15,4.4 42.45,4.4 44.7,6.65 47.53,6.65 CN3.8
PRED_EN_A: length 62.8
  TOP w0.24: IC35.6 35.1,42.6 34.85,42.35 33.62,42.35 C155.1
  TOP w0.3: v2(64.8,39.65) 64.3,40.15 IC46.6 ; v2(64.8,39.65) 66.05,40.9 66.05,43.4 64.8,44.65 64.8,46.9 62.25,49.45 IC47.6 60.25,49.45 60,49.2 60,48.69 59.21,47.9 58.4,47.9 58.05,47.55 IC44.1 ; v2(64.8,39.65) 65.25,39.2 65.25,37.25 64.55,36.55 IC49.7 63.25,36.55 63.1,36.4 63.1,36.2 63.25,36.05 IC49.6 ; C155.1 33.5,41.65 34.15,41 37.2,41 37.74,41.54 41.99,41.54 43.6,43.15 45.65,43.15 46.2,42.6 50.2,42.6 v2(50.9,43.3)
  BOTTOM w0.3: v2(64.8,39.65) 61.4,43.05 54.45,43.05 53.4,44.1 51.7,44.1 v2(50.9,43.3)
PRED_EN_B: length 88.8
  TOP w0.24: C158.1 73.62,7.85 75.09,7.85 75.5,8.26 IC39.6
  TOP w0.3: IC58.6 v2(24.45,15.1) ; IC56.1 v2(30.05,9.75) 28.35,9.75 26.2,11.9 v2(25.75,11.9) 25.75,10.45 25.25,9.95 24.65,9.95 24.45,9.75 IC59.6 ; C158.1 73.5,7.2 74.25,6.45 v2(75.5,6.45)
  BOTTOM w0.3: v2(75.5,6.45) 75.5,7.7 75.9,8.1 78.35,8.1 78.95,8.7 78.95,14 77.65,15.3 71.25,15.3 66.1,20.45 63,20.45 60.65,18.1 51,18.1 50.2,18.9 48.85,18.9 47.95,18 42.39,18 35.14,10.75 31.05,10.75 v2(30.05,9.75) ; v2(25.75,11.9) 24.45,13.2 IC58.6 v2(24.45,15.1) 24.1,15.1 23.95,14.95 IC61.6
